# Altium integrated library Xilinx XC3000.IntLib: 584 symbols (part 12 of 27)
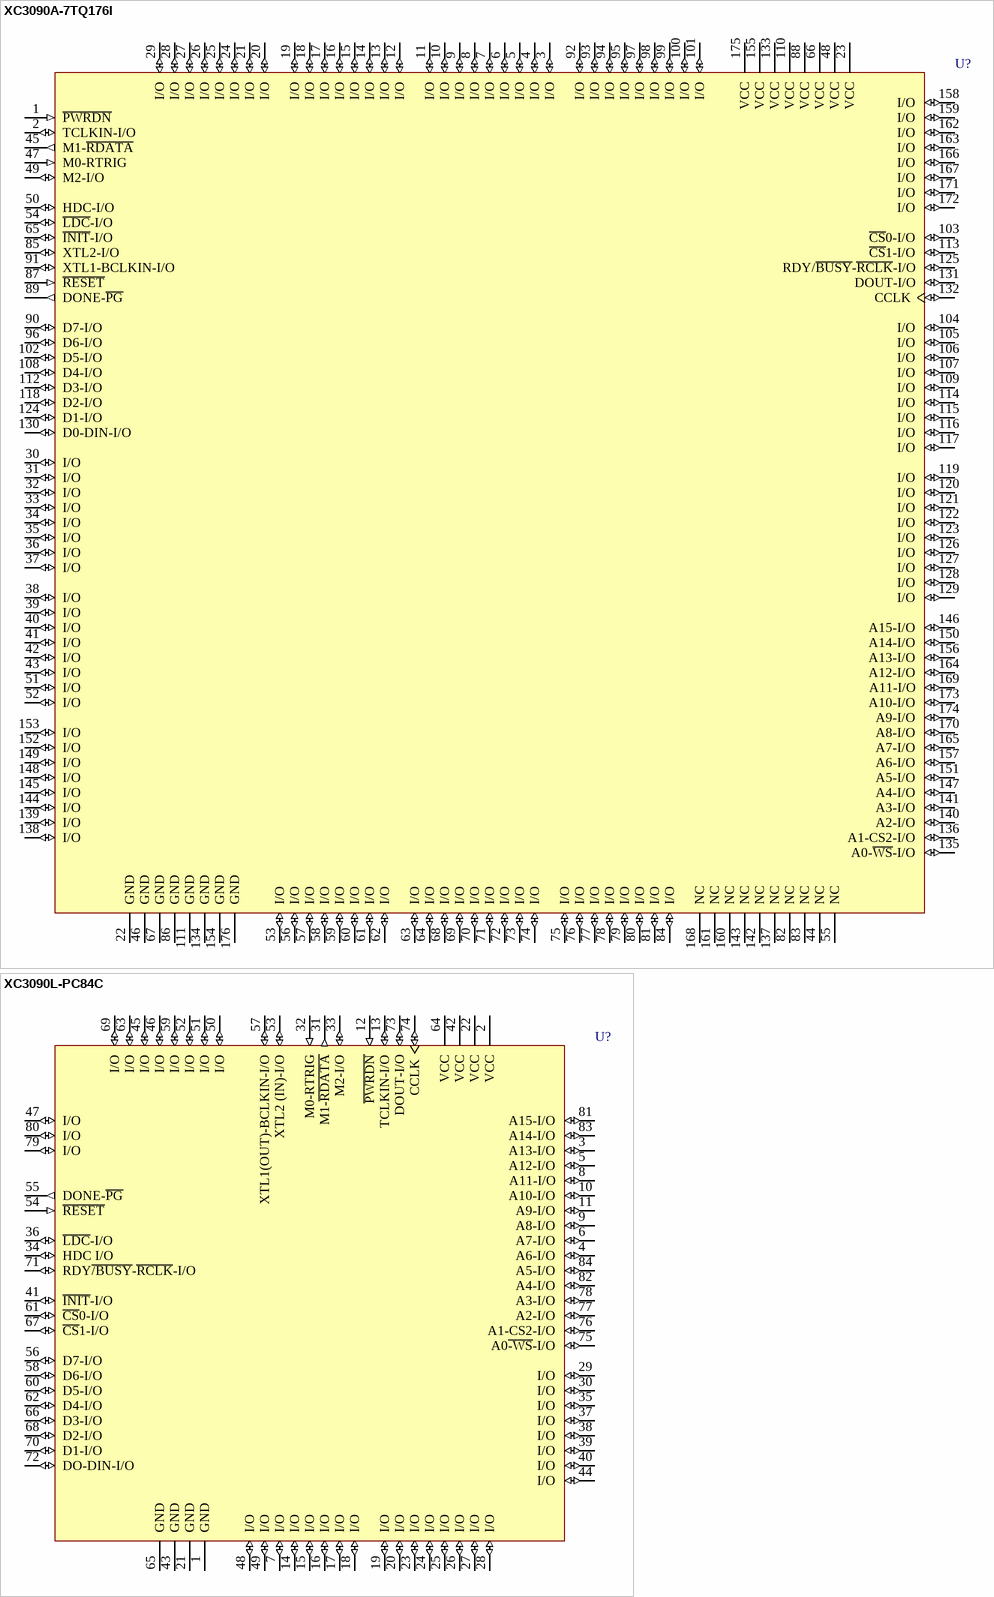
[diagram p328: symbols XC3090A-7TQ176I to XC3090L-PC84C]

## XC3090A-7TQ176I
designator U?
Logic Cell Array with 320 CLBs, with 144 I/O Pins, 176-Pin TQFP, Industrial Grade; ComponentAvailability: Not for New Design
footprint TQ176_N (Thin QFP, 176-Leads, Body 24x24mm, Pitch 0.5mm, IPC Medium Density)
footprint TQ176_L (Thin QFP, 176-Leads, Body 24x24mm, Pitch 0.5mm, IPC High Density)
footprint TQ176_M (Thin QFP, 176-Leads, Body 24x24mm, Pitch 0.5mm, IPC Low Density)
3D model XC3090A-TQ176 (176-Pin Thin Quad Flat Pack (TQ176))
pins: 1 ~{PWRDN} (in), 2 TCLKIN-I/O (io), 3 I/O (io), 4 I/O (io), 5 I/O (io), 6 I/O (io), 7 I/O (io), 8 I/O (io), 9 I/O (io), 10 I/O (io), 11 I/O (io), 12 I/O (io), 13 I/O (io), 14 I/O (io), 15 I/O (io), 16 I/O (io), 17 I/O (io), 18 I/O (io), 19 I/O (io), 20 I/O (io), 21 I/O (io), 22 GND (power), 23 VCC (power), 24 I/O (io), 25 I/O (io), 26 I/O (io), 27 I/O (io), 28 I/O (io), 29 I/O (io), 30 I/O (io), 31 I/O (io), 32 I/O (io), 33 I/O (io), 34 I/O (io), 35 I/O (io), 36 I/O (io), 37 I/O (io), 38 I/O (io), 39 I/O (io), 40 I/O (io), 41 I/O (io), 42 I/O (io), 43 I/O (io), 44 NC, 45 M1-~{RDATA} (out), 46 GND (power), 47 M0-RTRIG (in), 48 VCC (power), 49 M2-I/O (io), 50 HDC-I/O (io), 51 I/O (io), 52 I/O (io), 53 I/O (io), 54 ~{LDC}-I/O (io), 55 NC, 56 I/O (io), 57 I/O (io), 58 I/O (io), 59 I/O (io), 60 I/O (io), 61 I/O (io), 62 I/O (io), 63 I/O (io), 64 I/O (io), 65 ~{INIT}-I/O (io), 66 VCC (power), 67 GND (power), 68 I/O (io), 69 I/O (io), 70 I/O (io), 71 I/O (io), 72 I/O (io), 73 I/O (io), 74 I/O (io), 75 I/O (io), 76 I/O (io), 77 I/O (io), 78 I/O (io), 79 I/O (io), 80 I/O (io), 81 I/O (io), 82 NC, 83 NC, 84 I/O (io), 85 XTL2-I/O (io), 86 GND (power), 87 ~{RESET} (in), 88 VCC (power), 89 DONE-~{PG} (out), 90 D7-I/O (io), 91 XTL1-BCLKIN-I/O (io), 92 I/O (io), 93 I/O (io), 94 I/O (io), 95 I/O (io), 96 D6-I/O (io), 97 I/O (io), 98 I/O (io), 99 I/O (io), 100 I/O (io), 101 I/O (io), 102 D5-I/O (io), 103 ~{CS}0-I/O (io), 104 I/O (io), 105 I/O (io), 106 I/O (io), 107 I/O (io), 108 D4-I/O (io), 109 I/O (io), 110 VCC (power), 111 GND (power), 112 D3-I/O (io), 113 ~{CS}1-I/O (io), 114 I/O (io), 115 I/O (io), 116 I/O (io), 117 I/O (io), 118 D2-I/O (io), 119 I/O (io), 120 I/O (io), 121 I/O (io), 122 I/O (io), 123 I/O (io), 124 D1-I/O (io), 125 RDY/~{BUSY}-~{RCLK}-I/O (io), 126 I/O (io), 127 I/O (io), 128 I/O (io), 129 I/O (io), 130 D0-DIN-I/O (io), 131 DOUT-I/O (io), 132 CCLK (io), 133 VCC (power), 134 GND (power), 135 A0-~{WS}-I/O (io), 136 A1-CS2-I/O (io), 137 NC, 138 I/O (io), 139 I/O (io), 140 A2-I/O (io), 141 A3-I/O (io), 142 NC, 143 NC, 144 I/O (io), 145 I/O (io), 146 A15-I/O (io), 147 A4-I/O (io), 148 I/O (io), 149 I/O (io), 150 A14-I/O (io), 151 A5-I/O (io), 152 I/O (io), 153 I/O (io), 154 GND (power), 155 VCC (power), 156 A13-I/O (io), 157 A6-I/O (io), 158 I/O (io), 159 I/O (io), 160 NC, 161 NC, 162 I/O (io), 163 I/O (io), 164 A12-I/O (io), 165 A7-I/O (io), 166 I/O (io), 167 I/O (io), 168 NC, 169 A11-I/O (io), 170 A8-I/O (io), 171 I/O (io), 172 I/O (io), 173 A10-I/O (io), 174 A9-I/O (io), 175 VCC (power), 176 GND (power)

## XC3090L-PC84C
designator U?
Logic Cell Array with 320 CLBs, with 70 I/O Pins, 84-Pin PLCC, Commercial Grade; ComponentAvailability: Not for New Design
footprint PC84_N (Leaded Chip Carrier, 84-Leads, Body 29.3x29.3mm, Pitch 1.27mm, IPC Medium Density)
footprint PC84_L (Leaded Chip Carrier, 84-Leads, Body 29.3x29.3mm, Pitch 1.27mm, IPC High Density)
footprint PC84_M (Leaded Chip Carrier, 84-Leads, Body 29.3x29.3mm, Pitch 1.27mm, IPC Low Density)
3D model XC3090L-PC84 (84-Pin Plastic Leaded Chip Carrier (PC84))
pins: 1 GND (power), 2 VCC (power), 3 A13-I/O (io), 4 A6-I/O (io), 5 A12-I/O (io), 6 A7-I/O (io), 7 I/O (io), 8 A11-I/O (io), 9 A8-I/O (io), 10 A10-I/O (io), 11 A9-I/O (io), 12 ~{PWRDN} (in), 13 TCLKIN-I/O (io), 14 I/O (io), 15 I/O (io), 16 I/O (io), 17 I/O (io), 18 I/O (io), 19 I/O (io), 20 I/O (io), 21 GND (power), 22 VCC (power), 23 I/O (io), 24 I/O (io), 25 I/O (io), 26 I/O (io), 27 I/O (io), 28 I/O (io), 29 I/O (io), 30 I/O (io), 31 M1-~{RDATA} (out), 32 M0-RTRIG (in), 33 M2-I/O (io), 34 HDC I/O (io), 35 I/O (io), 36 ~{LDC}-I/O (io), 37 I/O (io), 38 I/O (io), 39 I/O (io), 40 I/O (io), 41 ~{INIT}-I/O (io), 42 VCC (power), 43 GND (power), 44 I/O (io), 45 I/O (io), 46 I/O (io), 47 I/O (io), 48 I/O (io), 49 I/O (io), 50 I/O (io), 51 I/O (io), 52 I/O (io), 53 XTL2 (IN)-I/O (io), 54 ~{RESET} (in), 55 DONE-~{PG} (out), 56 D7-I/O (io), 57 XTL1(OUT)-BCLKIN-I/O (io), 58 D6-I/O (io), 59 I/O (io), 60 D5-I/O (io), 61 ~{CS}0-I/O (io), 62 D4-I/O (io), 63 I/O (io), 64 VCC (power), 65 GND (power), 66 D3-I/O (io), 67 ~{CS}1-I/O (io), 68 D2-I/O (io), 69 I/O (io), 70 D1-I/O (io), 71 RDY~{/BUSY}-~{RCLK}-I/O (io), 72 DO-DIN-I/O (io), 73 DOUT-I/O (io), 74 CCLK (io), 75 A0~{-WS}-I/O (io), 76 A1-CS2-I/O (io), 77 A2-I/O (io), 78 A3-I/O (io), 79 I/O (io), 80 I/O (io), 81 A15-I/O (io), 82 A4-I/O (io), 83 A14-I/O (io), 84 A5-I/O (io)

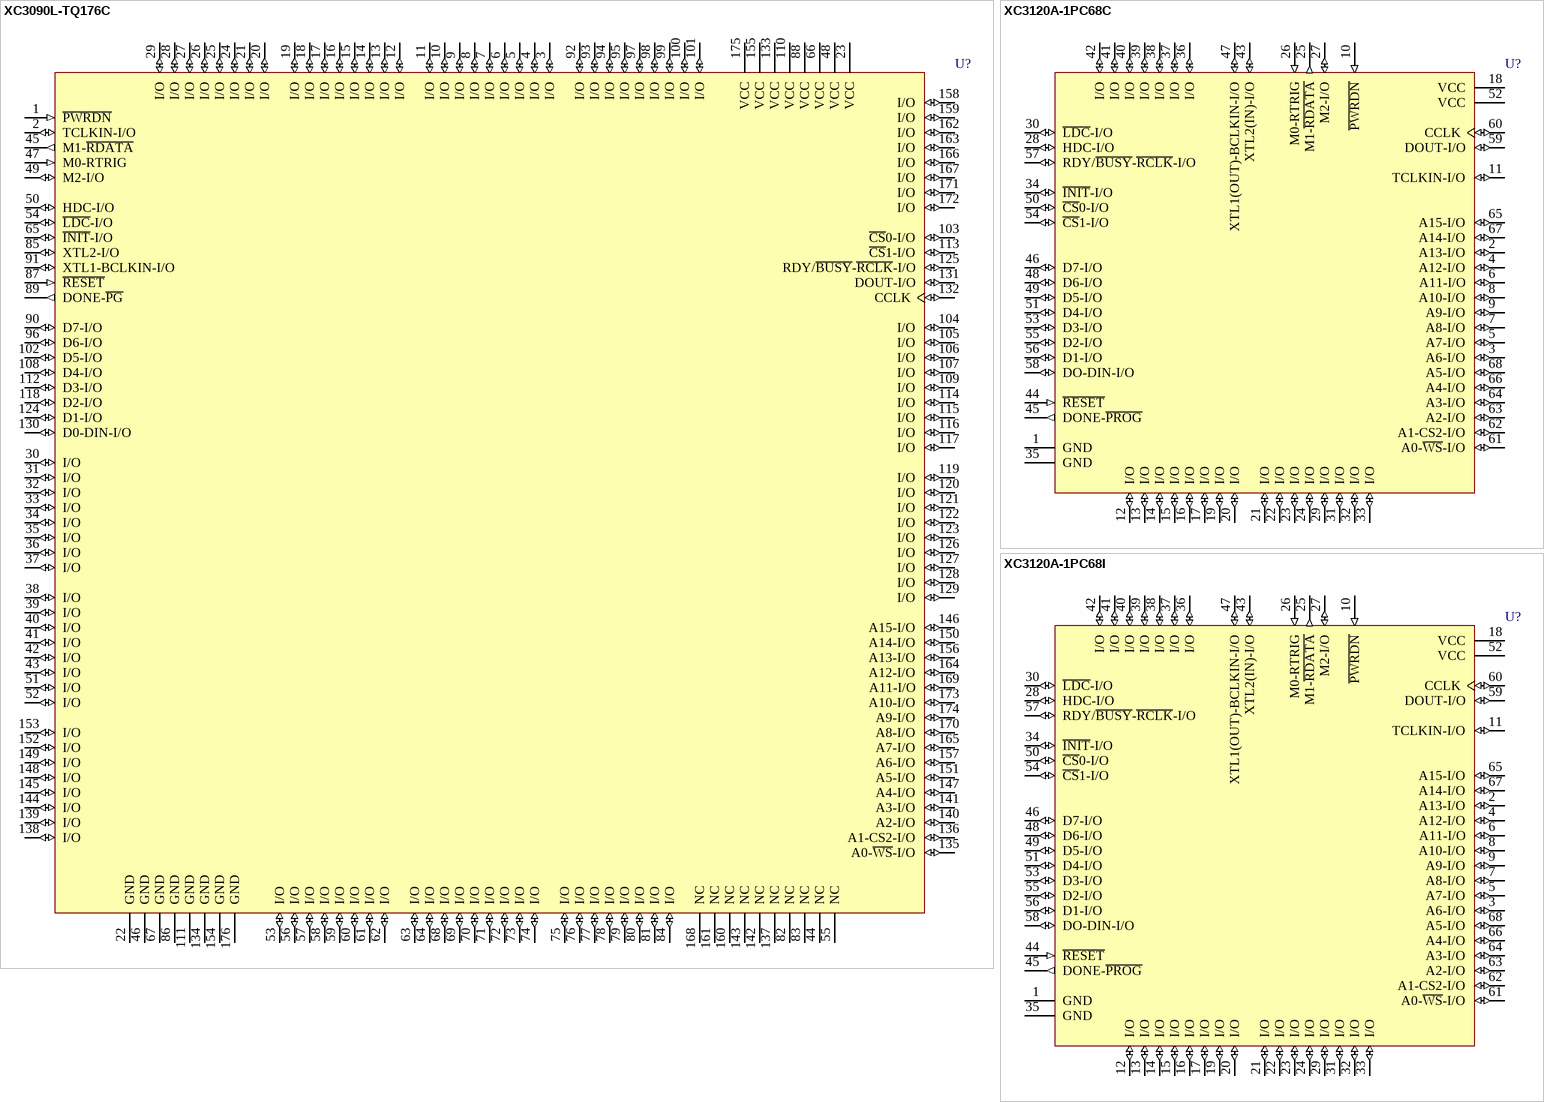
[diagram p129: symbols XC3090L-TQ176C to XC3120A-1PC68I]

## XC3090L-TQ176C
designator U?
Logic Cell Array with 320 CLBs, with 144 I/O Pins, 176-Pin TQFP, Commercial Grade; ComponentAvailability: Not for New Design
footprint TQ176_N (Thin QFP, 176-Leads, Body 24x24mm, Pitch 0.5mm, IPC Medium Density)
footprint TQ176_L (Thin QFP, 176-Leads, Body 24x24mm, Pitch 0.5mm, IPC High Density)
footprint TQ176_M (Thin QFP, 176-Leads, Body 24x24mm, Pitch 0.5mm, IPC Low Density)
3D model XC3090L-TQ176 (176-Pin Thin Quad Flat Pack (TQ176))
pins: 1 ~{PWRDN} (in), 2 TCLKIN-I/O (io), 3 I/O (io), 4 I/O (io), 5 I/O (io), 6 I/O (io), 7 I/O (io), 8 I/O (io), 9 I/O (io), 10 I/O (io), 11 I/O (io), 12 I/O (io), 13 I/O (io), 14 I/O (io), 15 I/O (io), 16 I/O (io), 17 I/O (io), 18 I/O (io), 19 I/O (io), 20 I/O (io), 21 I/O (io), 22 GND (power), 23 VCC (power), 24 I/O (io), 25 I/O (io), 26 I/O (io), 27 I/O (io), 28 I/O (io), 29 I/O (io), 30 I/O (io), 31 I/O (io), 32 I/O (io), 33 I/O (io), 34 I/O (io), 35 I/O (io), 36 I/O (io), 37 I/O (io), 38 I/O (io), 39 I/O (io), 40 I/O (io), 41 I/O (io), 42 I/O (io), 43 I/O (io), 44 NC, 45 M1-~{RDATA} (out), 46 GND (power), 47 M0-RTRIG (in), 48 VCC (power), 49 M2-I/O (io), 50 HDC-I/O (io), 51 I/O (io), 52 I/O (io), 53 I/O (io), 54 ~{LDC}-I/O (io), 55 NC, 56 I/O (io), 57 I/O (io), 58 I/O (io), 59 I/O (io), 60 I/O (io), 61 I/O (io), 62 I/O (io), 63 I/O (io), 64 I/O (io), 65 ~{INIT}-I/O (io), 66 VCC (power), 67 GND (power), 68 I/O (io), 69 I/O (io), 70 I/O (io), 71 I/O (io), 72 I/O (io), 73 I/O (io), 74 I/O (io), 75 I/O (io), 76 I/O (io), 77 I/O (io), 78 I/O (io), 79 I/O (io), 80 I/O (io), 81 I/O (io), 82 NC, 83 NC, 84 I/O (io), 85 XTL2-I/O (io), 86 GND (power), 87 ~{RESET} (in), 88 VCC (power), 89 DONE-~{PG} (out), 90 D7-I/O (io), 91 XTL1-BCLKIN-I/O (io), 92 I/O (io), 93 I/O (io), 94 I/O (io), 95 I/O (io), 96 D6-I/O (io), 97 I/O (io), 98 I/O (io), 99 I/O (io), 100 I/O (io), 101 I/O (io), 102 D5-I/O (io), 103 ~{CS}0-I/O (io), 104 I/O (io), 105 I/O (io), 106 I/O (io), 107 I/O (io), 108 D4-I/O (io), 109 I/O (io), 110 VCC (power), 111 GND (power), 112 D3-I/O (io), 113 ~{CS}1-I/O (io), 114 I/O (io), 115 I/O (io), 116 I/O (io), 117 I/O (io), 118 D2-I/O (io), 119 I/O (io), 120 I/O (io), 121 I/O (io), 122 I/O (io), 123 I/O (io), 124 D1-I/O (io), 125 RDY/~{BUSY}-~{RCLK}-I/O (io), 126 I/O (io), 127 I/O (io), 128 I/O (io), 129 I/O (io), 130 D0-DIN-I/O (io), 131 DOUT-I/O (io), 132 CCLK (io), 133 VCC (power), 134 GND (power), 135 A0-~{WS}-I/O (io), 136 A1-CS2-I/O (io), 137 NC, 138 I/O (io), 139 I/O (io), 140 A2-I/O (io), 141 A3-I/O (io), 142 NC, 143 NC, 144 I/O (io), 145 I/O (io), 146 A15-I/O (io), 147 A4-I/O (io), 148 I/O (io), 149 I/O (io), 150 A14-I/O (io), 151 A5-I/O (io), 152 I/O (io), 153 I/O (io), 154 GND (power), 155 VCC (power), 156 A13-I/O (io), 157 A6-I/O (io), 158 I/O (io), 159 I/O (io), 160 NC, 161 NC, 162 I/O (io), 163 I/O (io), 164 A12-I/O (io), 165 A7-I/O (io), 166 I/O (io), 167 I/O (io), 168 NC, 169 A11-I/O (io), 170 A8-I/O (io), 171 I/O (io), 172 I/O (io), 173 A10-I/O (io), 174 A9-I/O (io), 175 VCC (power), 176 GND (power)

## XC3120A-1PC68C
designator U?
Logic Cell Array with 64 CLBs, with 58 I/O Pins, 68-Pin PLCC, Commercial Grade; ComponentAvailability: Not for New Design
footprint PC68_N (Leaded Chip Carrier, 68-Leads, Body 24x24mm, Pitch 1.27mm, IPC Medium Density)
footprint PC68_L (Leaded Chip Carrier, 68-Leads, Body 24x24mm, Pitch 1.27mm, IPC High Density)
footprint PC68_M (Leaded Chip Carrier, 68-Leads, Body 24x24mm, Pitch 1.27mm, IPC Low Density)
3D model XC3120A-PC68 (68-Pin Plastic Leaded Chip Carrier (PC68))
pins: 1 GND (power), 2 A13-I/O (io), 3 A6-I/O (io), 4 A12-I/O (io), 5 A7-I/O (io), 6 A11-I/O (io), 7 A8-I/O (io), 8 A10-I/O (io), 9 A9-I/O (io), 10 ~{PWRDN} (in), 11 TCLKIN-I/O (io), 12 I/O (io), 13 I/O (io), 14 I/O (io), 15 I/O (io), 16 I/O (io), 17 I/O (io), 18 VCC (power), 19 I/O (io), 20 I/O (io), 21 I/O (io), 22 I/O (io), 23 I/O (io), 24 I/O (io), 25 M1-~{RDATA} (out), 26 M0-RTRIG (in), 27 M2-I/O (io), 28 HDC-I/O (io), 29 I/O (io), 30 ~{LDC}-I/O (io), 31 I/O (io), 32 I/O (io), 33 I/O (io), 34 ~{INIT}-I/O (io), 35 GND (power), 36 I/O (io), 37 I/O (io), 38 I/O (io), 39 I/O (io), 40 I/O (io), 41 I/O (io), 42 I/O (io), 43 XTL2(IN)-I/O (io), 44 ~{RESET} (in), 45 DONE-~{PROG} (out), 46 D7-I/O (io), 47 XTL1(OUT)-BCLKIN-I/O (io), 48 D6-I/O (io), 49 D5-I/O (io), 50 ~{CS}0-I/O (io), 51 D4-I/O (io), 52 VCC (power), 53 D3-I/O (io), 54 ~{CS}1-I/O (io), 55 D2-I/O (io), 56 D1-I/O (io), 57 RDY/~{BUSY}-~{RCLK}-I/O (io), 58 DO-DIN-I/O (io), 59 DOUT-I/O (io), 60 CCLK (io), 61 A0-~{WS}-I/O (io), 62 A1-CS2-I/O (io), 63 A2-I/O (io), 64 A3-I/O (io), 65 A15-I/O (io), 66 A4-I/O (io), 67 A14-I/O (io), 68 A5-I/O (io)

## XC3120A-1PC68I
designator U?
Logic Cell Array with 64 CLBs, with 58 I/O Pins, 68-Pin PLCC, Industrial Grade; ComponentAvailability: Not for New Design
footprint PC68_N (Leaded Chip Carrier, 68-Leads, Body 24x24mm, Pitch 1.27mm, IPC Medium Density)
footprint PC68_L (Leaded Chip Carrier, 68-Leads, Body 24x24mm, Pitch 1.27mm, IPC High Density)
footprint PC68_M (Leaded Chip Carrier, 68-Leads, Body 24x24mm, Pitch 1.27mm, IPC Low Density)
3D model XC3120A-PC68 (68-Pin Plastic Leaded Chip Carrier (PC68))
pins: 1 GND (power), 2 A13-I/O (io), 3 A6-I/O (io), 4 A12-I/O (io), 5 A7-I/O (io), 6 A11-I/O (io), 7 A8-I/O (io), 8 A10-I/O (io), 9 A9-I/O (io), 10 ~{PWRDN} (in), 11 TCLKIN-I/O (io), 12 I/O (io), 13 I/O (io), 14 I/O (io), 15 I/O (io), 16 I/O (io), 17 I/O (io), 18 VCC (power), 19 I/O (io), 20 I/O (io), 21 I/O (io), 22 I/O (io), 23 I/O (io), 24 I/O (io), 25 M1-~{RDATA} (out), 26 M0-RTRIG (in), 27 M2-I/O (io), 28 HDC-I/O (io), 29 I/O (io), 30 ~{LDC}-I/O (io), 31 I/O (io), 32 I/O (io), 33 I/O (io), 34 ~{INIT}-I/O (io), 35 GND (power), 36 I/O (io), 37 I/O (io), 38 I/O (io), 39 I/O (io), 40 I/O (io), 41 I/O (io), 42 I/O (io), 43 XTL2(IN)-I/O (io), 44 ~{RESET} (in), 45 DONE-~{PROG} (out), 46 D7-I/O (io), 47 XTL1(OUT)-BCLKIN-I/O (io), 48 D6-I/O (io), 49 D5-I/O (io), 50 ~{CS}0-I/O (io), 51 D4-I/O (io), 52 VCC (power), 53 D3-I/O (io), 54 ~{CS}1-I/O (io), 55 D2-I/O (io), 56 D1-I/O (io), 57 RDY/~{BUSY}-~{RCLK}-I/O (io), 58 DO-DIN-I/O (io), 59 DOUT-I/O (io), 60 CCLK (io), 61 A0-~{WS}-I/O (io), 62 A1-CS2-I/O (io), 63 A2-I/O (io), 64 A3-I/O (io), 65 A15-I/O (io), 66 A4-I/O (io), 67 A14-I/O (io), 68 A5-I/O (io)

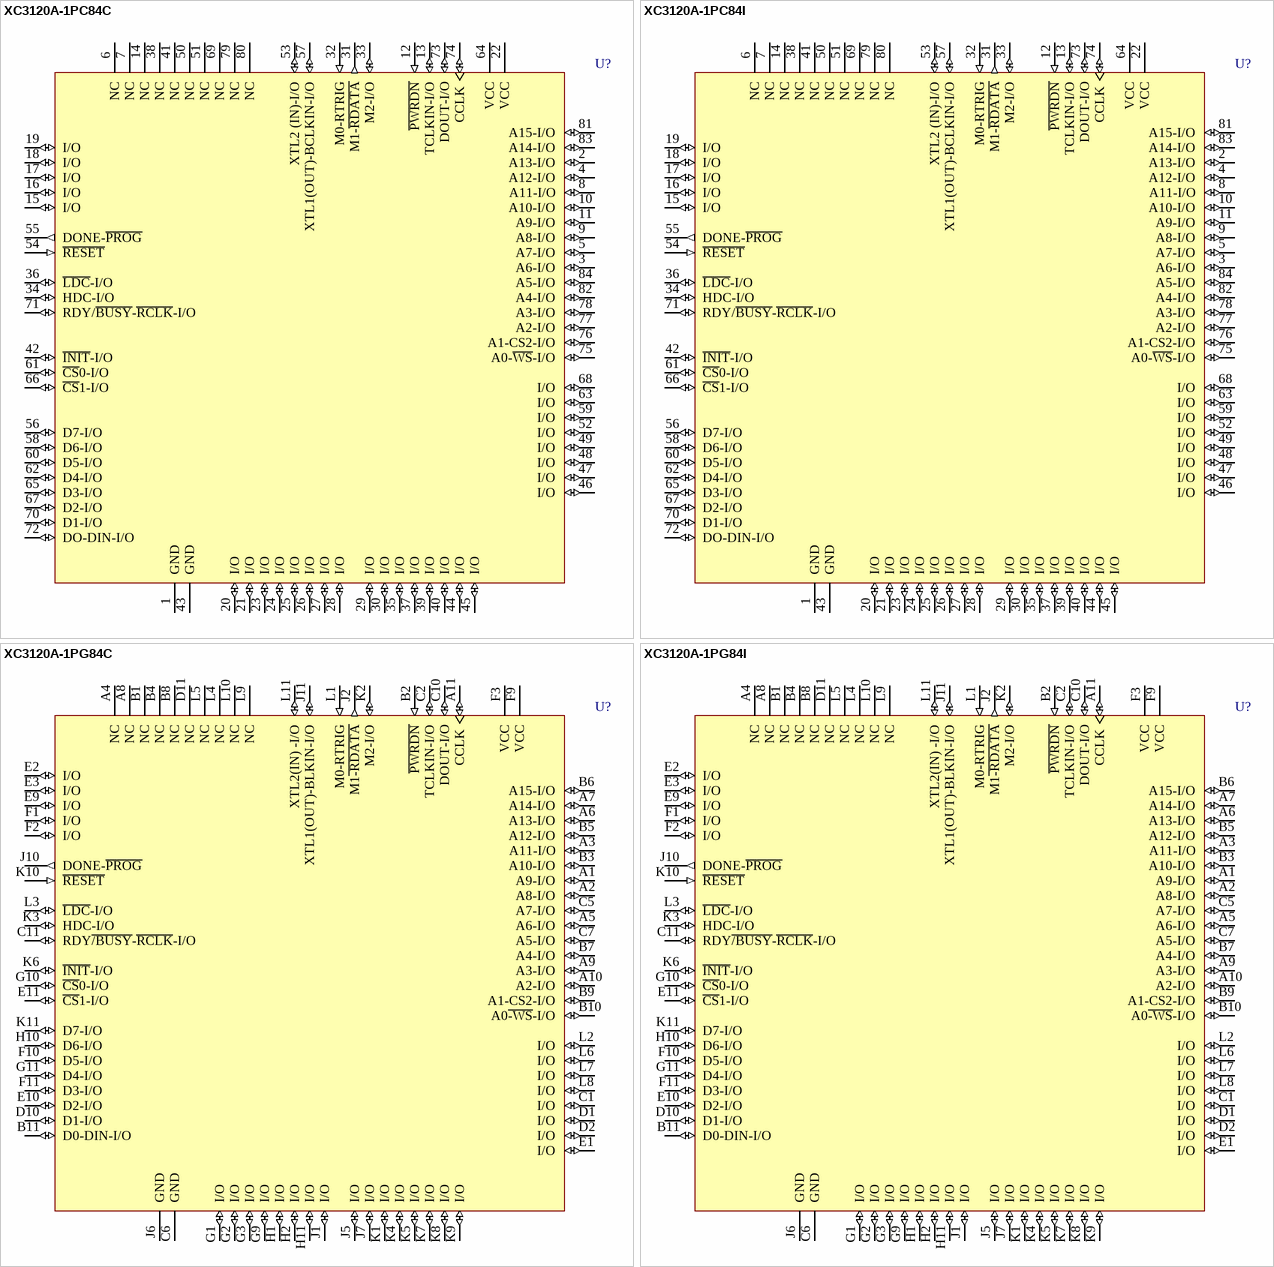
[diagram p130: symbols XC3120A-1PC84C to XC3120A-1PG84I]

## XC3120A-1PC84C
designator U?
Logic Cell Array with 64 CLBs, with 64 I/O Pins, 84-Pin PLCC, Commercial Grade; ComponentAvailability: Not for New Design
footprint PC84_N (Leaded Chip Carrier, 84-Leads, Body 29.3x29.3mm, Pitch 1.27mm, IPC Medium Density)
footprint PC84_L (Leaded Chip Carrier, 84-Leads, Body 29.3x29.3mm, Pitch 1.27mm, IPC High Density)
footprint PC84_M (Leaded Chip Carrier, 84-Leads, Body 29.3x29.3mm, Pitch 1.27mm, IPC Low Density)
3D model XC3120A-PC84 (84-Pin Plastic Leaded Chip Carrier (PC84))
pins: 1 GND (power), 2 A13-I/O (io), 3 A6-I/O (io), 4 A12-I/O (io), 5 A7-I/O (io), 6 NC, 7 NC, 8 A11-I/O (io), 9 A8-I/O (io), 10 A10-I/O (io), 11 A9-I/O (io), 12 ~{PWRDN} (in), 13 TCLKIN-I/O (io), 14 NC, 15 I/O (io), 16 I/O (io), 17 I/O (io), 18 I/O (io), 19 I/O (io), 20 I/O (io), 21 I/O (io), 22 VCC (power), 23 I/O (io), 24 I/O (io), 25 I/O (io), 26 I/O (io), 27 I/O (io), 28 I/O (io), 29 I/O (io), 30 I/O (io), 31 M1-~{RDATA} (out), 32 M0-RTRIG (in), 33 M2-I/O (io), 34 HDC-I/O (io), 35 I/O (io), 36 ~{LDC}-I/O (io), 37 I/O (io), 38 NC, 39 I/O (io), 40 I/O (io), 41 NC, 42 ~{INIT}-I/O (io), 43 GND (power), 44 I/O (io), 45 I/O (io), 46 I/O (io), 47 I/O (io), 48 I/O (io), 49 I/O (io), 50 NC, 51 NC, 52 I/O (io), 53 XTL2 (IN)-I/O (io), 54 ~{RESET} (in), 55 DONE-~{PROG} (out), 56 D7-I/O (io), 57 XTL1(OUT)-BCLKIN-I/O (io), 58 D6-I/O (io), 59 I/O (io), 60 D5-I/O (io), 61 ~{CS}0-I/O (io), 62 D4-I/O (io), 63 I/O (io), 64 VCC (power), 65 D3-I/O (io), 66 ~{CS}1-I/O (io), 67 D2-I/O (io), 68 I/O (io), 69 NC, 70 D1-I/O (io), 71 RDY/~{BUSY}-~{RCLK}-I/O (io), 72 DO-DIN-I/O (io), 73 DOUT-I/O (io), 74 CCLK (io), 75 A0-~{WS}-I/O (io), 76 A1-CS2-I/O (io), 77 A2-I/O (io), 78 A3-I/O (io), 79 NC, 80 NC, 81 A15-I/O (io), 82 A4-I/O (io), 83 A14-I/O (io), 84 A5-I/O (io)

## XC3120A-1PC84I
designator U?
Logic Cell Array with 64 CLBs, with 64 I/O Pins, 84-Pin PLCC, Industrial Grade; ComponentAvailability: Not for New Design
footprint PC84_N (Leaded Chip Carrier, 84-Leads, Body 29.3x29.3mm, Pitch 1.27mm, IPC Medium Density)
footprint PC84_L (Leaded Chip Carrier, 84-Leads, Body 29.3x29.3mm, Pitch 1.27mm, IPC High Density)
footprint PC84_M (Leaded Chip Carrier, 84-Leads, Body 29.3x29.3mm, Pitch 1.27mm, IPC Low Density)
3D model XC3120A-PC84 (84-Pin Plastic Leaded Chip Carrier (PC84))
pins: 1 GND (power), 2 A13-I/O (io), 3 A6-I/O (io), 4 A12-I/O (io), 5 A7-I/O (io), 6 NC, 7 NC, 8 A11-I/O (io), 9 A8-I/O (io), 10 A10-I/O (io), 11 A9-I/O (io), 12 ~{PWRDN} (in), 13 TCLKIN-I/O (io), 14 NC, 15 I/O (io), 16 I/O (io), 17 I/O (io), 18 I/O (io), 19 I/O (io), 20 I/O (io), 21 I/O (io), 22 VCC (power), 23 I/O (io), 24 I/O (io), 25 I/O (io), 26 I/O (io), 27 I/O (io), 28 I/O (io), 29 I/O (io), 30 I/O (io), 31 M1-~{RDATA} (out), 32 M0-RTRIG (in), 33 M2-I/O (io), 34 HDC-I/O (io), 35 I/O (io), 36 ~{LDC}-I/O (io), 37 I/O (io), 38 NC, 39 I/O (io), 40 I/O (io), 41 NC, 42 ~{INIT}-I/O (io), 43 GND (power), 44 I/O (io), 45 I/O (io), 46 I/O (io), 47 I/O (io), 48 I/O (io), 49 I/O (io), 50 NC, 51 NC, 52 I/O (io), 53 XTL2 (IN)-I/O (io), 54 ~{RESET} (in), 55 DONE-~{PROG} (out), 56 D7-I/O (io), 57 XTL1(OUT)-BCLKIN-I/O (io), 58 D6-I/O (io), 59 I/O (io), 60 D5-I/O (io), 61 ~{CS}0-I/O (io), 62 D4-I/O (io), 63 I/O (io), 64 VCC (power), 65 D3-I/O (io), 66 ~{CS}1-I/O (io), 67 D2-I/O (io), 68 I/O (io), 69 NC, 70 D1-I/O (io), 71 RDY/~{BUSY}-~{RCLK}-I/O (io), 72 DO-DIN-I/O (io), 73 DOUT-I/O (io), 74 CCLK (io), 75 A0-~{WS}-I/O (io), 76 A1-CS2-I/O (io), 77 A2-I/O (io), 78 A3-I/O (io), 79 NC, 80 NC, 81 A15-I/O (io), 82 A4-I/O (io), 83 A14-I/O (io), 84 A5-I/O (io)

## XC3120A-1PG84C
designator U?
Logic Cell Array with 64 CLBs, with 64 I/O Pins, 84-Pin PGA, Commercial Grade; ComponentAvailability: Not for New Design
footprint PG84 (PGA, 85-Leads, Body 28x28mm, Pitch 2.54mm)
3D model XC3120A-PG84 (84-Pin Ceramic Pin Grid Array (PG84))
pins: A1 A9-I/O (io), A2 A8-I/O (io), A3 A11-I/O (io), A4 NC, A5 A6-I/O (io), A6 A13-I/O (io), A7 A14-I/O (io), A8 NC, A9 A3-I/O (io), A10 A2-I/O (io), A11 CCLK (io), B1 NC, B2 ~{PWRDN} (in), B3 A10-I/O (io), B4 NC, B5 A12-I/O (io), B6 A15-I/O (io), B7 A4-I/O (io), B8 NC, B9 A1-CS2-I/O (io), B10 A0~{-WS}-I/O (io), B11 D0-DIN-I/O (io), C1 I/O (io), C2 TCLKIN-I/O (io), C5 A7-I/O (io), C6 GND (power), C7 A5-I/O (io), C10 DOUT-I/O (io), C11 RDY~{/BUSY}-~{RCLK}-I/O (io), D1 I/O (io), D2 I/O (io), D10 D1-I/O (io), D11 NC, E1 I/O (io), E2 I/O (io), E3 I/O (io), E9 I/O (io), E10 D2-I/O (io), E11 ~{CS}1-I/O (io), F1 I/O (io), F2 I/O (io), F3 VCC (power), F9 VCC (power), F10 D5-I/O (io), F11 D3-I/O (io), G1 I/O (io), G2 I/O (io), G3 I/O (io), G9 I/O (io), G10 ~{CS}0-I/O (io), G11 D4-I/O (io), H1 I/O (io), H2 I/O (io), H10 D6-I/O (io), H11 I/O (io), J1 I/O (io), J2 M1~{-RDATA} (out), J5 I/O (io), J6 GND (power), J7 I/O (io), J10 DONE-~{PROG} (out), J11 XTL1(OUT)-BLKIN-I/O (io), K1 I/O (io), K2 M2-I/O (io), K3 HDC-I/O (io), K4 I/O (io), K5 I/O (io), K6 ~{INIT}-I/O (io), K7 I/O (io), K8 I/O (io), K9 I/O (io), K10 ~{RESET} (in), K11 D7-I/O (io), L1 M0-RTRIG (in), L2 I/O (io), L3 ~{LDC}-I/O (io), L4 NC, L5 NC, L6 I/O (io), L7 I/O (io), L8 I/O (io), L9 NC, L10 NC, L11 XTL2(IN) -I/O (io)

## XC3120A-1PG84I
designator U?
Logic Cell Array with 64 CLBs, with 64 I/O Pins, 84-Pin PGA, Industrial Grade; ComponentAvailability: Not for New Design
footprint PG84 (PGA, 85-Leads, Body 28x28mm, Pitch 2.54mm)
3D model XC3120A-PG84 (84-Pin Ceramic Pin Grid Array (PG84))
pins: A1 A9-I/O (io), A2 A8-I/O (io), A3 A11-I/O (io), A4 NC, A5 A6-I/O (io), A6 A13-I/O (io), A7 A14-I/O (io), A8 NC, A9 A3-I/O (io), A10 A2-I/O (io), A11 CCLK (io), B1 NC, B2 ~{PWRDN} (in), B3 A10-I/O (io), B4 NC, B5 A12-I/O (io), B6 A15-I/O (io), B7 A4-I/O (io), B8 NC, B9 A1-CS2-I/O (io), B10 A0~{-WS}-I/O (io), B11 D0-DIN-I/O (io), C1 I/O (io), C2 TCLKIN-I/O (io), C5 A7-I/O (io), C6 GND (power), C7 A5-I/O (io), C10 DOUT-I/O (io), C11 RDY~{/BUSY}-~{RCLK}-I/O (io), D1 I/O (io), D2 I/O (io), D10 D1-I/O (io), D11 NC, E1 I/O (io), E2 I/O (io), E3 I/O (io), E9 I/O (io), E10 D2-I/O (io), E11 ~{CS}1-I/O (io), F1 I/O (io), F2 I/O (io), F3 VCC (power), F9 VCC (power), F10 D5-I/O (io), F11 D3-I/O (io), G1 I/O (io), G2 I/O (io), G3 I/O (io), G9 I/O (io), G10 ~{CS}0-I/O (io), G11 D4-I/O (io), H1 I/O (io), H2 I/O (io), H10 D6-I/O (io), H11 I/O (io), J1 I/O (io), J2 M1~{-RDATA} (out), J5 I/O (io), J6 GND (power), J7 I/O (io), J10 DONE-~{PROG} (out), J11 XTL1(OUT)-BLKIN-I/O (io), K1 I/O (io), K2 M2-I/O (io), K3 HDC-I/O (io), K4 I/O (io), K5 I/O (io), K6 ~{INIT}-I/O (io), K7 I/O (io), K8 I/O (io), K9 I/O (io), K10 ~{RESET} (in), K11 D7-I/O (io), L1 M0-RTRIG (in), L2 I/O (io), L3 ~{LDC}-I/O (io), L4 NC, L5 NC, L6 I/O (io), L7 I/O (io), L8 I/O (io), L9 NC, L10 NC, L11 XTL2(IN) -I/O (io)

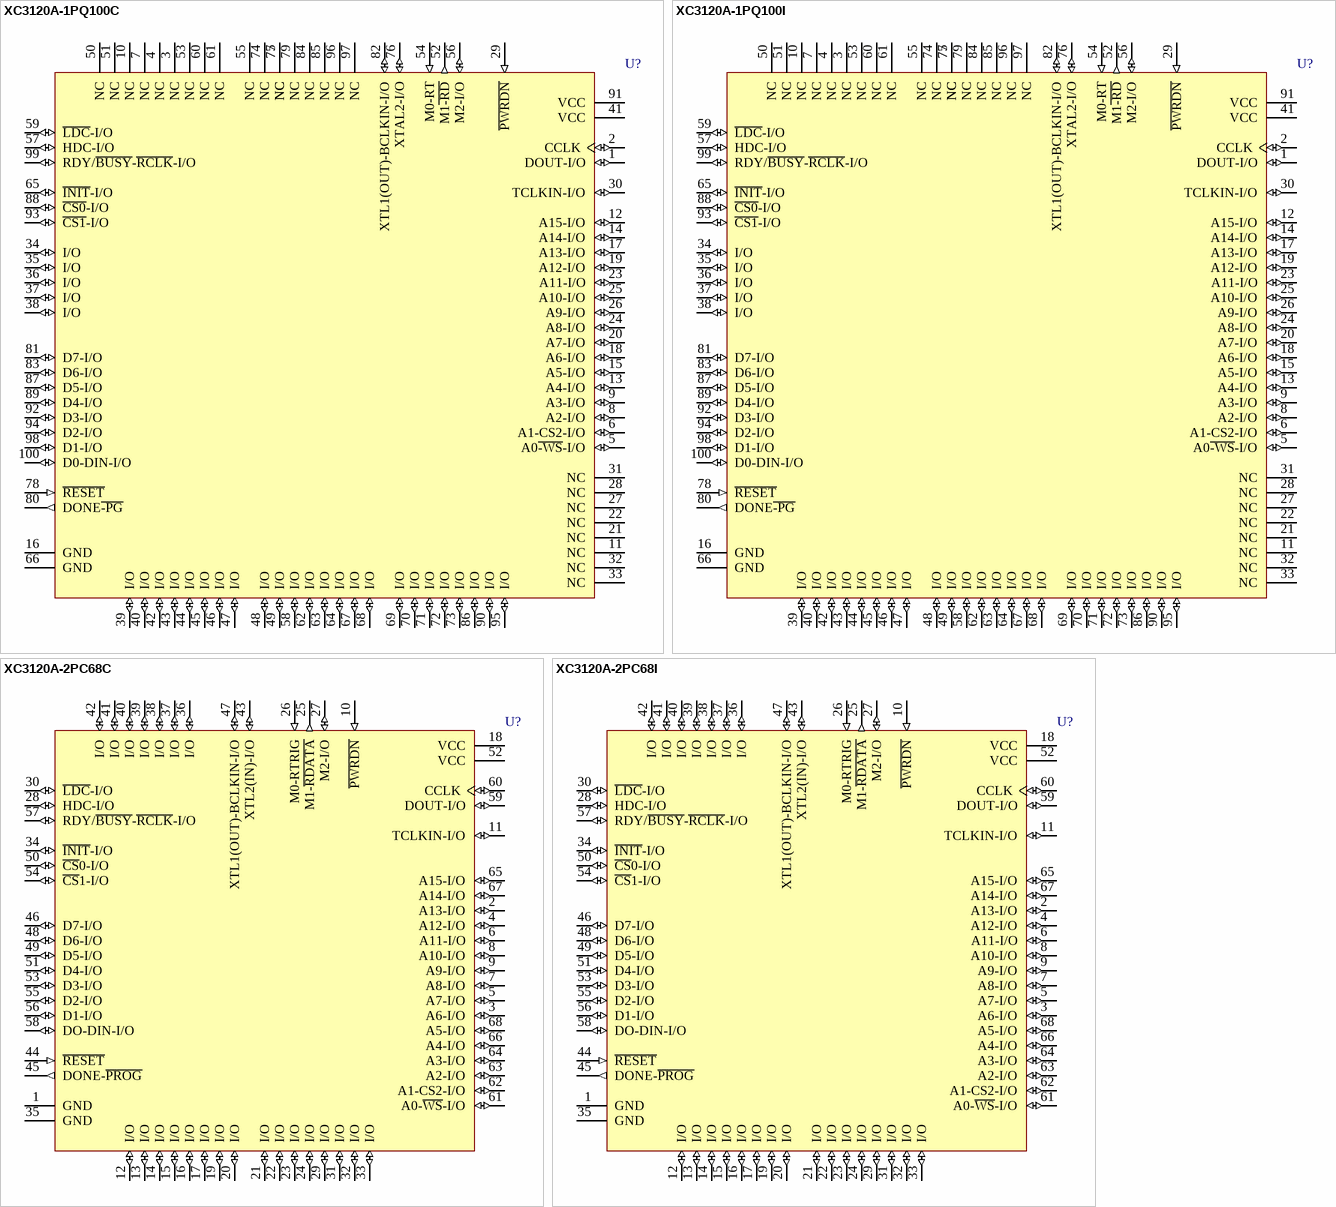
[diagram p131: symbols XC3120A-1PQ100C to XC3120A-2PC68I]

## XC3120A-1PQ100C
designator U?
Logic Cell Array with 64 CLBs, with 64 I/O Pins, 100-Pin PQFP, Commercial Grade; ComponentAvailability: Not for New Design
footprint PQ100_N (QFP, 100-Leads, Body 20x14mm, Pitch 0.65mm, IPC Medium Density)
footprint PQ100_L (QFP, 100-Leads, Body 20x14mm, Pitch 0.65mm, IPC High Density)
footprint PQ100_M (QFP, 100-Leads, Body 20x14mm, Pitch 0.65mm, IPC Low Density)
3D model XC3120A-PQ100 (100-Pin Plastic Quad Flat Pack (PQ100))
pins: 1 DOUT-I/O (io), 2 CCLK (io), 3 NC, 4 NC, 5 A0~{-WS}-I/O (io), 6 A1-CS2-I/O (io), 7 NC, 8 A2-I/O (io), 9 A3-I/O (io), 10 NC, 11 NC, 12 A15-I/O (io), 13 A4-I/O (io), 14 A14-I/O (io), 15 A5-I/O (io), 16 GND (power), 17 A13-I/O (io), 18 A6-I/O (io), 19 A12-I/O (io), 20 A7-I/O (io), 21 NC, 22 NC, 23 A11-I/O (io), 24 A8-I/O (io), 25 A10-I/O (io), 26 A9-I/O (io), 27 NC, 28 NC, 29 ~{PWRDN} (in), 30 TCLKIN-I/O (io), 31 NC, 32 NC, 33 NC, 34 I/O (io), 35 I/O (io), 36 I/O (io), 37 I/O (io), 38 I/O (io), 39 I/O (io), 40 I/O (io), 41 VCC (power), 42 I/O (io), 43 I/O (io), 44 I/O (io), 45 I/O (io), 46 I/O (io), 47 I/O (io), 48 I/O (io), 49 I/O (io), 50 NC, 51 NC, 52 M1~{-RD} (out), 53 NC, 54 M0-RT (in), 55 NC, 56 M2-I/O (io), 57 HDC-I/O (io), 58 I/O (io), 59 ~{LDC}-I/O (io), 60 NC, 61 NC, 62 I/O (io), 63 I/O (io), 64 I/O (io), 65 ~{INIT}-I/O (io), 66 GND (power), 67 I/O (io), 68 I/O (io), 69 I/O (io), 70 I/O (io), 71 I/O (io), 72 I/O (io), 73 I/O (io), 74 NC, 75 NC, 76 XTAL2-I/O (io), 77 NC, 78 ~{RESET} (in), 79 NC, 80 DONE~{-PG} (out), 81 D7-I/O (io), 82 XTL1(OUT)-BCLKIN-I/O (io), 83 D6-I/O (io), 84 NC, 85 NC, 86 I/O (io), 87 D5-I/O (io), 88 ~{CS0}-I/O (io), 89 D4-I/O (io), 90 I/O (io), 91 VCC (power), 92 D3-I/O (io), 93 ~{CS1}-I/O (io), 94 D2-I/O (io), 95 I/O (io), 96 NC, 97 NC, 98 D1-I/O (io), 99 RDY/~{BUSY}-~{RCLK}-I/O (io), 100 D0-DIN-I/O (io)

## XC3120A-1PQ100I
designator U?
Logic Cell Array with 64 CLBs, with 64 I/O Pins, 100-Pin PQFP, Industrial Grade; ComponentAvailability: Not for New Design
footprint PQ100_N (QFP, 100-Leads, Body 20x14mm, Pitch 0.65mm, IPC Medium Density)
footprint PQ100_L (QFP, 100-Leads, Body 20x14mm, Pitch 0.65mm, IPC High Density)
footprint PQ100_M (QFP, 100-Leads, Body 20x14mm, Pitch 0.65mm, IPC Low Density)
3D model XC3120A-PQ100 (100-Pin Plastic Quad Flat Pack (PQ100))
pins: 1 DOUT-I/O (io), 2 CCLK (io), 3 NC, 4 NC, 5 A0~{-WS}-I/O (io), 6 A1-CS2-I/O (io), 7 NC, 8 A2-I/O (io), 9 A3-I/O (io), 10 NC, 11 NC, 12 A15-I/O (io), 13 A4-I/O (io), 14 A14-I/O (io), 15 A5-I/O (io), 16 GND (power), 17 A13-I/O (io), 18 A6-I/O (io), 19 A12-I/O (io), 20 A7-I/O (io), 21 NC, 22 NC, 23 A11-I/O (io), 24 A8-I/O (io), 25 A10-I/O (io), 26 A9-I/O (io), 27 NC, 28 NC, 29 ~{PWRDN} (in), 30 TCLKIN-I/O (io), 31 NC, 32 NC, 33 NC, 34 I/O (io), 35 I/O (io), 36 I/O (io), 37 I/O (io), 38 I/O (io), 39 I/O (io), 40 I/O (io), 41 VCC (power), 42 I/O (io), 43 I/O (io), 44 I/O (io), 45 I/O (io), 46 I/O (io), 47 I/O (io), 48 I/O (io), 49 I/O (io), 50 NC, 51 NC, 52 M1~{-RD} (out), 53 NC, 54 M0-RT (in), 55 NC, 56 M2-I/O (io), 57 HDC-I/O (io), 58 I/O (io), 59 ~{LDC}-I/O (io), 60 NC, 61 NC, 62 I/O (io), 63 I/O (io), 64 I/O (io), 65 ~{INIT}-I/O (io), 66 GND (power), 67 I/O (io), 68 I/O (io), 69 I/O (io), 70 I/O (io), 71 I/O (io), 72 I/O (io), 73 I/O (io), 74 NC, 75 NC, 76 XTAL2-I/O (io), 77 NC, 78 ~{RESET} (in), 79 NC, 80 DONE~{-PG} (out), 81 D7-I/O (io), 82 XTL1(OUT)-BCLKIN-I/O (io), 83 D6-I/O (io), 84 NC, 85 NC, 86 I/O (io), 87 D5-I/O (io), 88 ~{CS0}-I/O (io), 89 D4-I/O (io), 90 I/O (io), 91 VCC (power), 92 D3-I/O (io), 93 ~{CS1}-I/O (io), 94 D2-I/O (io), 95 I/O (io), 96 NC, 97 NC, 98 D1-I/O (io), 99 RDY/~{BUSY}-~{RCLK}-I/O (io), 100 D0-DIN-I/O (io)

## XC3120A-2PC68C
designator U?
Logic Cell Array with 64 CLBs, with 58 I/O Pins, 68-Pin PLCC, Commercial Grade; ComponentAvailability: Not for New Design
footprint PC68_N (Leaded Chip Carrier, 68-Leads, Body 24x24mm, Pitch 1.27mm, IPC Medium Density)
footprint PC68_L (Leaded Chip Carrier, 68-Leads, Body 24x24mm, Pitch 1.27mm, IPC High Density)
footprint PC68_M (Leaded Chip Carrier, 68-Leads, Body 24x24mm, Pitch 1.27mm, IPC Low Density)
3D model XC3120A-PC68 (68-Pin Plastic Leaded Chip Carrier (PC68))
pins: 1 GND (power), 2 A13-I/O (io), 3 A6-I/O (io), 4 A12-I/O (io), 5 A7-I/O (io), 6 A11-I/O (io), 7 A8-I/O (io), 8 A10-I/O (io), 9 A9-I/O (io), 10 ~{PWRDN} (in), 11 TCLKIN-I/O (io), 12 I/O (io), 13 I/O (io), 14 I/O (io), 15 I/O (io), 16 I/O (io), 17 I/O (io), 18 VCC (power), 19 I/O (io), 20 I/O (io), 21 I/O (io), 22 I/O (io), 23 I/O (io), 24 I/O (io), 25 M1-~{RDATA} (out), 26 M0-RTRIG (in), 27 M2-I/O (io), 28 HDC-I/O (io), 29 I/O (io), 30 ~{LDC}-I/O (io), 31 I/O (io), 32 I/O (io), 33 I/O (io), 34 ~{INIT}-I/O (io), 35 GND (power), 36 I/O (io), 37 I/O (io), 38 I/O (io), 39 I/O (io), 40 I/O (io), 41 I/O (io), 42 I/O (io), 43 XTL2(IN)-I/O (io), 44 ~{RESET} (in), 45 DONE-~{PROG} (out), 46 D7-I/O (io), 47 XTL1(OUT)-BCLKIN-I/O (io), 48 D6-I/O (io), 49 D5-I/O (io), 50 ~{CS}0-I/O (io), 51 D4-I/O (io), 52 VCC (power), 53 D3-I/O (io), 54 ~{CS}1-I/O (io), 55 D2-I/O (io), 56 D1-I/O (io), 57 RDY/~{BUSY}-~{RCLK}-I/O (io), 58 DO-DIN-I/O (io), 59 DOUT-I/O (io), 60 CCLK (io), 61 A0-~{WS}-I/O (io), 62 A1-CS2-I/O (io), 63 A2-I/O (io), 64 A3-I/O (io), 65 A15-I/O (io), 66 A4-I/O (io), 67 A14-I/O (io), 68 A5-I/O (io)

## XC3120A-2PC68I
designator U?
Logic Cell Array with 64 CLBs, with 58 I/O Pins, 68-Pin PLCC, Industrial Grade; ComponentAvailability: Not for New Design
footprint PC68_N (Leaded Chip Carrier, 68-Leads, Body 24x24mm, Pitch 1.27mm, IPC Medium Density)
footprint PC68_L (Leaded Chip Carrier, 68-Leads, Body 24x24mm, Pitch 1.27mm, IPC High Density)
footprint PC68_M (Leaded Chip Carrier, 68-Leads, Body 24x24mm, Pitch 1.27mm, IPC Low Density)
3D model XC3120A-PC68 (68-Pin Plastic Leaded Chip Carrier (PC68))
pins: 1 GND (power), 2 A13-I/O (io), 3 A6-I/O (io), 4 A12-I/O (io), 5 A7-I/O (io), 6 A11-I/O (io), 7 A8-I/O (io), 8 A10-I/O (io), 9 A9-I/O (io), 10 ~{PWRDN} (in), 11 TCLKIN-I/O (io), 12 I/O (io), 13 I/O (io), 14 I/O (io), 15 I/O (io), 16 I/O (io), 17 I/O (io), 18 VCC (power), 19 I/O (io), 20 I/O (io), 21 I/O (io), 22 I/O (io), 23 I/O (io), 24 I/O (io), 25 M1-~{RDATA} (out), 26 M0-RTRIG (in), 27 M2-I/O (io), 28 HDC-I/O (io), 29 I/O (io), 30 ~{LDC}-I/O (io), 31 I/O (io), 32 I/O (io), 33 I/O (io), 34 ~{INIT}-I/O (io), 35 GND (power), 36 I/O (io), 37 I/O (io), 38 I/O (io), 39 I/O (io), 40 I/O (io), 41 I/O (io), 42 I/O (io), 43 XTL2(IN)-I/O (io), 44 ~{RESET} (in), 45 DONE-~{PROG} (out), 46 D7-I/O (io), 47 XTL1(OUT)-BCLKIN-I/O (io), 48 D6-I/O (io), 49 D5-I/O (io), 50 ~{CS}0-I/O (io), 51 D4-I/O (io), 52 VCC (power), 53 D3-I/O (io), 54 ~{CS}1-I/O (io), 55 D2-I/O (io), 56 D1-I/O (io), 57 RDY/~{BUSY}-~{RCLK}-I/O (io), 58 DO-DIN-I/O (io), 59 DOUT-I/O (io), 60 CCLK (io), 61 A0-~{WS}-I/O (io), 62 A1-CS2-I/O (io), 63 A2-I/O (io), 64 A3-I/O (io), 65 A15-I/O (io), 66 A4-I/O (io), 67 A14-I/O (io), 68 A5-I/O (io)

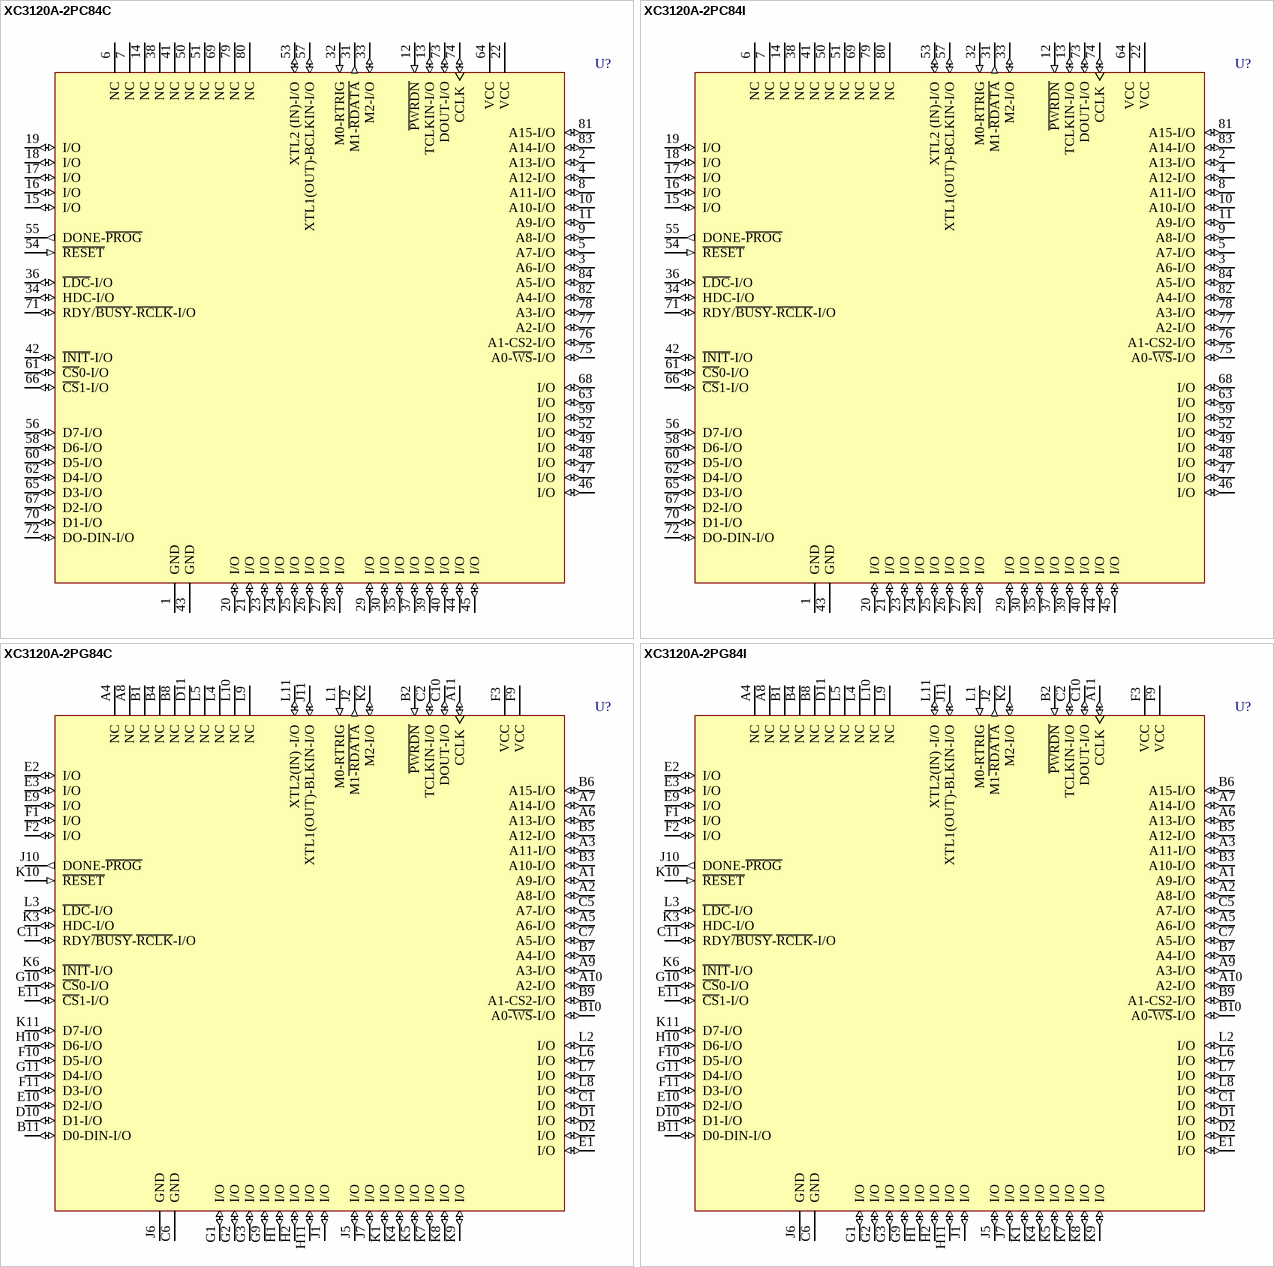
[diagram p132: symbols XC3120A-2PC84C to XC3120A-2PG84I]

## XC3120A-2PC84C
designator U?
Logic Cell Array with 64 CLBs, with 64 I/O Pins, 84-Pin PLCC, Commercial Grade; ComponentAvailability: Not for New Design
footprint PC84_N (Leaded Chip Carrier, 84-Leads, Body 29.3x29.3mm, Pitch 1.27mm, IPC Medium Density)
footprint PC84_L (Leaded Chip Carrier, 84-Leads, Body 29.3x29.3mm, Pitch 1.27mm, IPC High Density)
footprint PC84_M (Leaded Chip Carrier, 84-Leads, Body 29.3x29.3mm, Pitch 1.27mm, IPC Low Density)
3D model XC3120A-PC84 (84-Pin Plastic Leaded Chip Carrier (PC84))
pins: 1 GND (power), 2 A13-I/O (io), 3 A6-I/O (io), 4 A12-I/O (io), 5 A7-I/O (io), 6 NC, 7 NC, 8 A11-I/O (io), 9 A8-I/O (io), 10 A10-I/O (io), 11 A9-I/O (io), 12 ~{PWRDN} (in), 13 TCLKIN-I/O (io), 14 NC, 15 I/O (io), 16 I/O (io), 17 I/O (io), 18 I/O (io), 19 I/O (io), 20 I/O (io), 21 I/O (io), 22 VCC (power), 23 I/O (io), 24 I/O (io), 25 I/O (io), 26 I/O (io), 27 I/O (io), 28 I/O (io), 29 I/O (io), 30 I/O (io), 31 M1-~{RDATA} (out), 32 M0-RTRIG (in), 33 M2-I/O (io), 34 HDC-I/O (io), 35 I/O (io), 36 ~{LDC}-I/O (io), 37 I/O (io), 38 NC, 39 I/O (io), 40 I/O (io), 41 NC, 42 ~{INIT}-I/O (io), 43 GND (power), 44 I/O (io), 45 I/O (io), 46 I/O (io), 47 I/O (io), 48 I/O (io), 49 I/O (io), 50 NC, 51 NC, 52 I/O (io), 53 XTL2 (IN)-I/O (io), 54 ~{RESET} (in), 55 DONE-~{PROG} (out), 56 D7-I/O (io), 57 XTL1(OUT)-BCLKIN-I/O (io), 58 D6-I/O (io), 59 I/O (io), 60 D5-I/O (io), 61 ~{CS}0-I/O (io), 62 D4-I/O (io), 63 I/O (io), 64 VCC (power), 65 D3-I/O (io), 66 ~{CS}1-I/O (io), 67 D2-I/O (io), 68 I/O (io), 69 NC, 70 D1-I/O (io), 71 RDY/~{BUSY}-~{RCLK}-I/O (io), 72 DO-DIN-I/O (io), 73 DOUT-I/O (io), 74 CCLK (io), 75 A0-~{WS}-I/O (io), 76 A1-CS2-I/O (io), 77 A2-I/O (io), 78 A3-I/O (io), 79 NC, 80 NC, 81 A15-I/O (io), 82 A4-I/O (io), 83 A14-I/O (io), 84 A5-I/O (io)

## XC3120A-2PC84I
designator U?
Logic Cell Array with 64 CLBs, with 64 I/O Pins, 84-Pin PLCC, Industrial Grade; ComponentAvailability: Not for New Design
footprint PC84_N (Leaded Chip Carrier, 84-Leads, Body 29.3x29.3mm, Pitch 1.27mm, IPC Medium Density)
footprint PC84_L (Leaded Chip Carrier, 84-Leads, Body 29.3x29.3mm, Pitch 1.27mm, IPC High Density)
footprint PC84_M (Leaded Chip Carrier, 84-Leads, Body 29.3x29.3mm, Pitch 1.27mm, IPC Low Density)
3D model XC3120A-PC84 (84-Pin Plastic Leaded Chip Carrier (PC84))
pins: 1 GND (power), 2 A13-I/O (io), 3 A6-I/O (io), 4 A12-I/O (io), 5 A7-I/O (io), 6 NC, 7 NC, 8 A11-I/O (io), 9 A8-I/O (io), 10 A10-I/O (io), 11 A9-I/O (io), 12 ~{PWRDN} (in), 13 TCLKIN-I/O (io), 14 NC, 15 I/O (io), 16 I/O (io), 17 I/O (io), 18 I/O (io), 19 I/O (io), 20 I/O (io), 21 I/O (io), 22 VCC (power), 23 I/O (io), 24 I/O (io), 25 I/O (io), 26 I/O (io), 27 I/O (io), 28 I/O (io), 29 I/O (io), 30 I/O (io), 31 M1-~{RDATA} (out), 32 M0-RTRIG (in), 33 M2-I/O (io), 34 HDC-I/O (io), 35 I/O (io), 36 ~{LDC}-I/O (io), 37 I/O (io), 38 NC, 39 I/O (io), 40 I/O (io), 41 NC, 42 ~{INIT}-I/O (io), 43 GND (power), 44 I/O (io), 45 I/O (io), 46 I/O (io), 47 I/O (io), 48 I/O (io), 49 I/O (io), 50 NC, 51 NC, 52 I/O (io), 53 XTL2 (IN)-I/O (io), 54 ~{RESET} (in), 55 DONE-~{PROG} (out), 56 D7-I/O (io), 57 XTL1(OUT)-BCLKIN-I/O (io), 58 D6-I/O (io), 59 I/O (io), 60 D5-I/O (io), 61 ~{CS}0-I/O (io), 62 D4-I/O (io), 63 I/O (io), 64 VCC (power), 65 D3-I/O (io), 66 ~{CS}1-I/O (io), 67 D2-I/O (io), 68 I/O (io), 69 NC, 70 D1-I/O (io), 71 RDY/~{BUSY}-~{RCLK}-I/O (io), 72 DO-DIN-I/O (io), 73 DOUT-I/O (io), 74 CCLK (io), 75 A0-~{WS}-I/O (io), 76 A1-CS2-I/O (io), 77 A2-I/O (io), 78 A3-I/O (io), 79 NC, 80 NC, 81 A15-I/O (io), 82 A4-I/O (io), 83 A14-I/O (io), 84 A5-I/O (io)

## XC3120A-2PG84C
designator U?
Logic Cell Array with 64 CLBs, with 64 I/O Pins, 84-Pin PGA, Commercial Grade; ComponentAvailability: Not for New Design
footprint PG84 (PGA, 85-Leads, Body 28x28mm, Pitch 2.54mm)
3D model XC3120A-PG84 (84-Pin Ceramic Pin Grid Array (PG84))
pins: A1 A9-I/O (io), A2 A8-I/O (io), A3 A11-I/O (io), A4 NC, A5 A6-I/O (io), A6 A13-I/O (io), A7 A14-I/O (io), A8 NC, A9 A3-I/O (io), A10 A2-I/O (io), A11 CCLK (io), B1 NC, B2 ~{PWRDN} (in), B3 A10-I/O (io), B4 NC, B5 A12-I/O (io), B6 A15-I/O (io), B7 A4-I/O (io), B8 NC, B9 A1-CS2-I/O (io), B10 A0~{-WS}-I/O (io), B11 D0-DIN-I/O (io), C1 I/O (io), C2 TCLKIN-I/O (io), C5 A7-I/O (io), C6 GND (power), C7 A5-I/O (io), C10 DOUT-I/O (io), C11 RDY~{/BUSY}-~{RCLK}-I/O (io), D1 I/O (io), D2 I/O (io), D10 D1-I/O (io), D11 NC, E1 I/O (io), E2 I/O (io), E3 I/O (io), E9 I/O (io), E10 D2-I/O (io), E11 ~{CS}1-I/O (io), F1 I/O (io), F2 I/O (io), F3 VCC (power), F9 VCC (power), F10 D5-I/O (io), F11 D3-I/O (io), G1 I/O (io), G2 I/O (io), G3 I/O (io), G9 I/O (io), G10 ~{CS}0-I/O (io), G11 D4-I/O (io), H1 I/O (io), H2 I/O (io), H10 D6-I/O (io), H11 I/O (io), J1 I/O (io), J2 M1~{-RDATA} (out), J5 I/O (io), J6 GND (power), J7 I/O (io), J10 DONE-~{PROG} (out), J11 XTL1(OUT)-BLKIN-I/O (io), K1 I/O (io), K2 M2-I/O (io), K3 HDC-I/O (io), K4 I/O (io), K5 I/O (io), K6 ~{INIT}-I/O (io), K7 I/O (io), K8 I/O (io), K9 I/O (io), K10 ~{RESET} (in), K11 D7-I/O (io), L1 M0-RTRIG (in), L2 I/O (io), L3 ~{LDC}-I/O (io), L4 NC, L5 NC, L6 I/O (io), L7 I/O (io), L8 I/O (io), L9 NC, L10 NC, L11 XTL2(IN) -I/O (io)

## XC3120A-2PG84I
designator U?
Logic Cell Array with 64 CLBs, with 64 I/O Pins, 84-Pin PGA, Industrial Grade; ComponentAvailability: Not for New Design
footprint PG84 (PGA, 85-Leads, Body 28x28mm, Pitch 2.54mm)
3D model XC3120A-PG84 (84-Pin Ceramic Pin Grid Array (PG84))
pins: A1 A9-I/O (io), A2 A8-I/O (io), A3 A11-I/O (io), A4 NC, A5 A6-I/O (io), A6 A13-I/O (io), A7 A14-I/O (io), A8 NC, A9 A3-I/O (io), A10 A2-I/O (io), A11 CCLK (io), B1 NC, B2 ~{PWRDN} (in), B3 A10-I/O (io), B4 NC, B5 A12-I/O (io), B6 A15-I/O (io), B7 A4-I/O (io), B8 NC, B9 A1-CS2-I/O (io), B10 A0~{-WS}-I/O (io), B11 D0-DIN-I/O (io), C1 I/O (io), C2 TCLKIN-I/O (io), C5 A7-I/O (io), C6 GND (power), C7 A5-I/O (io), C10 DOUT-I/O (io), C11 RDY~{/BUSY}-~{RCLK}-I/O (io), D1 I/O (io), D2 I/O (io), D10 D1-I/O (io), D11 NC, E1 I/O (io), E2 I/O (io), E3 I/O (io), E9 I/O (io), E10 D2-I/O (io), E11 ~{CS}1-I/O (io), F1 I/O (io), F2 I/O (io), F3 VCC (power), F9 VCC (power), F10 D5-I/O (io), F11 D3-I/O (io), G1 I/O (io), G2 I/O (io), G3 I/O (io), G9 I/O (io), G10 ~{CS}0-I/O (io), G11 D4-I/O (io), H1 I/O (io), H2 I/O (io), H10 D6-I/O (io), H11 I/O (io), J1 I/O (io), J2 M1~{-RDATA} (out), J5 I/O (io), J6 GND (power), J7 I/O (io), J10 DONE-~{PROG} (out), J11 XTL1(OUT)-BLKIN-I/O (io), K1 I/O (io), K2 M2-I/O (io), K3 HDC-I/O (io), K4 I/O (io), K5 I/O (io), K6 ~{INIT}-I/O (io), K7 I/O (io), K8 I/O (io), K9 I/O (io), K10 ~{RESET} (in), K11 D7-I/O (io), L1 M0-RTRIG (in), L2 I/O (io), L3 ~{LDC}-I/O (io), L4 NC, L5 NC, L6 I/O (io), L7 I/O (io), L8 I/O (io), L9 NC, L10 NC, L11 XTL2(IN) -I/O (io)

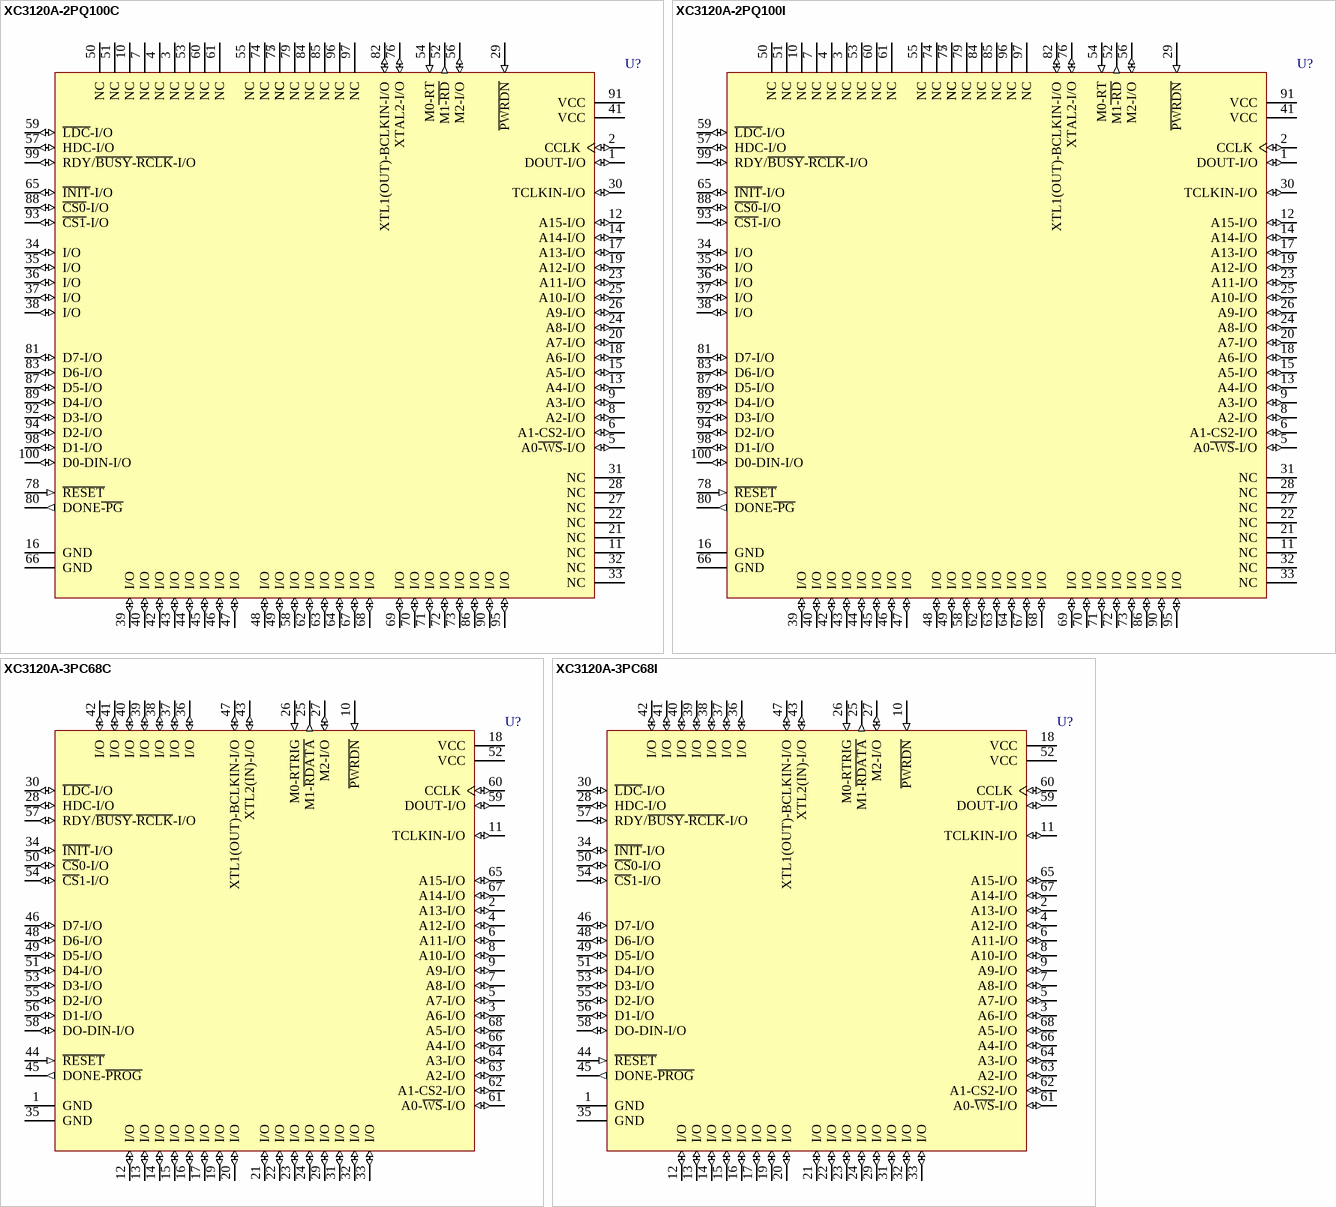
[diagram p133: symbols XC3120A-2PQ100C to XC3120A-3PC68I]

## XC3120A-2PQ100C
designator U?
Logic Cell Array with 64 CLBs, with 64 I/O Pins, 100-Pin PQFP, Commercial Grade; ComponentAvailability: Not for New Design
footprint PQ100_N (QFP, 100-Leads, Body 20x14mm, Pitch 0.65mm, IPC Medium Density)
footprint PQ100_L (QFP, 100-Leads, Body 20x14mm, Pitch 0.65mm, IPC High Density)
footprint PQ100_M (QFP, 100-Leads, Body 20x14mm, Pitch 0.65mm, IPC Low Density)
3D model XC3120A-PQ100 (100-Pin Plastic Quad Flat Pack (PQ100))
pins: 1 DOUT-I/O (io), 2 CCLK (io), 3 NC, 4 NC, 5 A0~{-WS}-I/O (io), 6 A1-CS2-I/O (io), 7 NC, 8 A2-I/O (io), 9 A3-I/O (io), 10 NC, 11 NC, 12 A15-I/O (io), 13 A4-I/O (io), 14 A14-I/O (io), 15 A5-I/O (io), 16 GND (power), 17 A13-I/O (io), 18 A6-I/O (io), 19 A12-I/O (io), 20 A7-I/O (io), 21 NC, 22 NC, 23 A11-I/O (io), 24 A8-I/O (io), 25 A10-I/O (io), 26 A9-I/O (io), 27 NC, 28 NC, 29 ~{PWRDN} (in), 30 TCLKIN-I/O (io), 31 NC, 32 NC, 33 NC, 34 I/O (io), 35 I/O (io), 36 I/O (io), 37 I/O (io), 38 I/O (io), 39 I/O (io), 40 I/O (io), 41 VCC (power), 42 I/O (io), 43 I/O (io), 44 I/O (io), 45 I/O (io), 46 I/O (io), 47 I/O (io), 48 I/O (io), 49 I/O (io), 50 NC, 51 NC, 52 M1~{-RD} (out), 53 NC, 54 M0-RT (in), 55 NC, 56 M2-I/O (io), 57 HDC-I/O (io), 58 I/O (io), 59 ~{LDC}-I/O (io), 60 NC, 61 NC, 62 I/O (io), 63 I/O (io), 64 I/O (io), 65 ~{INIT}-I/O (io), 66 GND (power), 67 I/O (io), 68 I/O (io), 69 I/O (io), 70 I/O (io), 71 I/O (io), 72 I/O (io), 73 I/O (io), 74 NC, 75 NC, 76 XTAL2-I/O (io), 77 NC, 78 ~{RESET} (in), 79 NC, 80 DONE~{-PG} (out), 81 D7-I/O (io), 82 XTL1(OUT)-BCLKIN-I/O (io), 83 D6-I/O (io), 84 NC, 85 NC, 86 I/O (io), 87 D5-I/O (io), 88 ~{CS0}-I/O (io), 89 D4-I/O (io), 90 I/O (io), 91 VCC (power), 92 D3-I/O (io), 93 ~{CS1}-I/O (io), 94 D2-I/O (io), 95 I/O (io), 96 NC, 97 NC, 98 D1-I/O (io), 99 RDY/~{BUSY}-~{RCLK}-I/O (io), 100 D0-DIN-I/O (io)

## XC3120A-2PQ100I
designator U?
Logic Cell Array with 64 CLBs, with 64 I/O Pins, 100-Pin PQFP, Industrial Grade; ComponentAvailability: Not for New Design
footprint PQ100_N (QFP, 100-Leads, Body 20x14mm, Pitch 0.65mm, IPC Medium Density)
footprint PQ100_L (QFP, 100-Leads, Body 20x14mm, Pitch 0.65mm, IPC High Density)
footprint PQ100_M (QFP, 100-Leads, Body 20x14mm, Pitch 0.65mm, IPC Low Density)
3D model XC3120A-PQ100 (100-Pin Plastic Quad Flat Pack (PQ100))
pins: 1 DOUT-I/O (io), 2 CCLK (io), 3 NC, 4 NC, 5 A0~{-WS}-I/O (io), 6 A1-CS2-I/O (io), 7 NC, 8 A2-I/O (io), 9 A3-I/O (io), 10 NC, 11 NC, 12 A15-I/O (io), 13 A4-I/O (io), 14 A14-I/O (io), 15 A5-I/O (io), 16 GND (power), 17 A13-I/O (io), 18 A6-I/O (io), 19 A12-I/O (io), 20 A7-I/O (io), 21 NC, 22 NC, 23 A11-I/O (io), 24 A8-I/O (io), 25 A10-I/O (io), 26 A9-I/O (io), 27 NC, 28 NC, 29 ~{PWRDN} (in), 30 TCLKIN-I/O (io), 31 NC, 32 NC, 33 NC, 34 I/O (io), 35 I/O (io), 36 I/O (io), 37 I/O (io), 38 I/O (io), 39 I/O (io), 40 I/O (io), 41 VCC (power), 42 I/O (io), 43 I/O (io), 44 I/O (io), 45 I/O (io), 46 I/O (io), 47 I/O (io), 48 I/O (io), 49 I/O (io), 50 NC, 51 NC, 52 M1~{-RD} (out), 53 NC, 54 M0-RT (in), 55 NC, 56 M2-I/O (io), 57 HDC-I/O (io), 58 I/O (io), 59 ~{LDC}-I/O (io), 60 NC, 61 NC, 62 I/O (io), 63 I/O (io), 64 I/O (io), 65 ~{INIT}-I/O (io), 66 GND (power), 67 I/O (io), 68 I/O (io), 69 I/O (io), 70 I/O (io), 71 I/O (io), 72 I/O (io), 73 I/O (io), 74 NC, 75 NC, 76 XTAL2-I/O (io), 77 NC, 78 ~{RESET} (in), 79 NC, 80 DONE~{-PG} (out), 81 D7-I/O (io), 82 XTL1(OUT)-BCLKIN-I/O (io), 83 D6-I/O (io), 84 NC, 85 NC, 86 I/O (io), 87 D5-I/O (io), 88 ~{CS0}-I/O (io), 89 D4-I/O (io), 90 I/O (io), 91 VCC (power), 92 D3-I/O (io), 93 ~{CS1}-I/O (io), 94 D2-I/O (io), 95 I/O (io), 96 NC, 97 NC, 98 D1-I/O (io), 99 RDY/~{BUSY}-~{RCLK}-I/O (io), 100 D0-DIN-I/O (io)

## XC3120A-3PC68C
designator U?
Logic Cell Array with 64 CLBs, with 58 I/O Pins, 68-Pin PLCC, Commercial Grade; ComponentAvailability: Not for New Design
footprint PC68_N (Leaded Chip Carrier, 68-Leads, Body 24x24mm, Pitch 1.27mm, IPC Medium Density)
footprint PC68_L (Leaded Chip Carrier, 68-Leads, Body 24x24mm, Pitch 1.27mm, IPC High Density)
footprint PC68_M (Leaded Chip Carrier, 68-Leads, Body 24x24mm, Pitch 1.27mm, IPC Low Density)
3D model XC3120A-PC68 (68-Pin Plastic Leaded Chip Carrier (PC68))
pins: 1 GND (power), 2 A13-I/O (io), 3 A6-I/O (io), 4 A12-I/O (io), 5 A7-I/O (io), 6 A11-I/O (io), 7 A8-I/O (io), 8 A10-I/O (io), 9 A9-I/O (io), 10 ~{PWRDN} (in), 11 TCLKIN-I/O (io), 12 I/O (io), 13 I/O (io), 14 I/O (io), 15 I/O (io), 16 I/O (io), 17 I/O (io), 18 VCC (power), 19 I/O (io), 20 I/O (io), 21 I/O (io), 22 I/O (io), 23 I/O (io), 24 I/O (io), 25 M1-~{RDATA} (out), 26 M0-RTRIG (in), 27 M2-I/O (io), 28 HDC-I/O (io), 29 I/O (io), 30 ~{LDC}-I/O (io), 31 I/O (io), 32 I/O (io), 33 I/O (io), 34 ~{INIT}-I/O (io), 35 GND (power), 36 I/O (io), 37 I/O (io), 38 I/O (io), 39 I/O (io), 40 I/O (io), 41 I/O (io), 42 I/O (io), 43 XTL2(IN)-I/O (io), 44 ~{RESET} (in), 45 DONE-~{PROG} (out), 46 D7-I/O (io), 47 XTL1(OUT)-BCLKIN-I/O (io), 48 D6-I/O (io), 49 D5-I/O (io), 50 ~{CS}0-I/O (io), 51 D4-I/O (io), 52 VCC (power), 53 D3-I/O (io), 54 ~{CS}1-I/O (io), 55 D2-I/O (io), 56 D1-I/O (io), 57 RDY/~{BUSY}-~{RCLK}-I/O (io), 58 DO-DIN-I/O (io), 59 DOUT-I/O (io), 60 CCLK (io), 61 A0-~{WS}-I/O (io), 62 A1-CS2-I/O (io), 63 A2-I/O (io), 64 A3-I/O (io), 65 A15-I/O (io), 66 A4-I/O (io), 67 A14-I/O (io), 68 A5-I/O (io)

## XC3120A-3PC68I
designator U?
Logic Cell Array with 64 CLBs, with 58 I/O Pins, 68-Pin PLCC, Industrial Grade; ComponentAvailability: Not for New Design
footprint PC68_N (Leaded Chip Carrier, 68-Leads, Body 24x24mm, Pitch 1.27mm, IPC Medium Density)
footprint PC68_L (Leaded Chip Carrier, 68-Leads, Body 24x24mm, Pitch 1.27mm, IPC High Density)
footprint PC68_M (Leaded Chip Carrier, 68-Leads, Body 24x24mm, Pitch 1.27mm, IPC Low Density)
3D model XC3120A-PC68 (68-Pin Plastic Leaded Chip Carrier (PC68))
pins: 1 GND (power), 2 A13-I/O (io), 3 A6-I/O (io), 4 A12-I/O (io), 5 A7-I/O (io), 6 A11-I/O (io), 7 A8-I/O (io), 8 A10-I/O (io), 9 A9-I/O (io), 10 ~{PWRDN} (in), 11 TCLKIN-I/O (io), 12 I/O (io), 13 I/O (io), 14 I/O (io), 15 I/O (io), 16 I/O (io), 17 I/O (io), 18 VCC (power), 19 I/O (io), 20 I/O (io), 21 I/O (io), 22 I/O (io), 23 I/O (io), 24 I/O (io), 25 M1-~{RDATA} (out), 26 M0-RTRIG (in), 27 M2-I/O (io), 28 HDC-I/O (io), 29 I/O (io), 30 ~{LDC}-I/O (io), 31 I/O (io), 32 I/O (io), 33 I/O (io), 34 ~{INIT}-I/O (io), 35 GND (power), 36 I/O (io), 37 I/O (io), 38 I/O (io), 39 I/O (io), 40 I/O (io), 41 I/O (io), 42 I/O (io), 43 XTL2(IN)-I/O (io), 44 ~{RESET} (in), 45 DONE-~{PROG} (out), 46 D7-I/O (io), 47 XTL1(OUT)-BCLKIN-I/O (io), 48 D6-I/O (io), 49 D5-I/O (io), 50 ~{CS}0-I/O (io), 51 D4-I/O (io), 52 VCC (power), 53 D3-I/O (io), 54 ~{CS}1-I/O (io), 55 D2-I/O (io), 56 D1-I/O (io), 57 RDY/~{BUSY}-~{RCLK}-I/O (io), 58 DO-DIN-I/O (io), 59 DOUT-I/O (io), 60 CCLK (io), 61 A0-~{WS}-I/O (io), 62 A1-CS2-I/O (io), 63 A2-I/O (io), 64 A3-I/O (io), 65 A15-I/O (io), 66 A4-I/O (io), 67 A14-I/O (io), 68 A5-I/O (io)

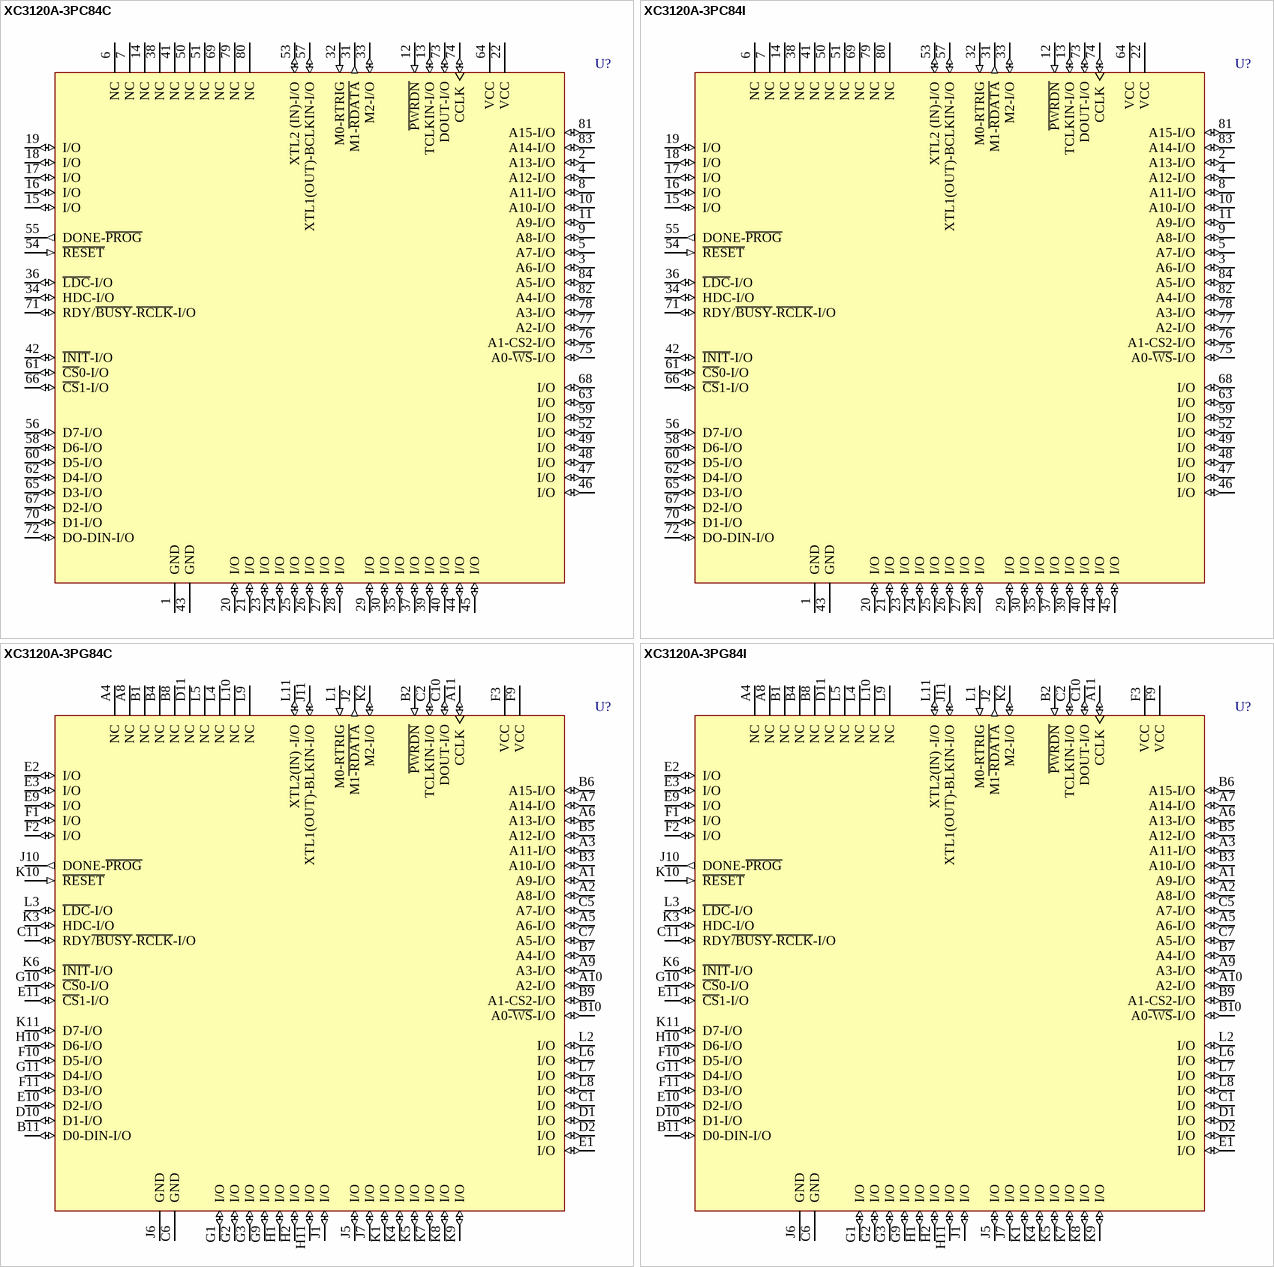
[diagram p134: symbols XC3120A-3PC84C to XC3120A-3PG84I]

## XC3120A-3PC84C
designator U?
Logic Cell Array with 64 CLBs, with 64 I/O Pins, 84-Pin PLCC, Commercial Grade; ComponentAvailability: Not for New Design
footprint PC84_N (Leaded Chip Carrier, 84-Leads, Body 29.3x29.3mm, Pitch 1.27mm, IPC Medium Density)
footprint PC84_L (Leaded Chip Carrier, 84-Leads, Body 29.3x29.3mm, Pitch 1.27mm, IPC High Density)
footprint PC84_M (Leaded Chip Carrier, 84-Leads, Body 29.3x29.3mm, Pitch 1.27mm, IPC Low Density)
3D model XC3120A-PC84 (84-Pin Plastic Leaded Chip Carrier (PC84))
pins: 1 GND (power), 2 A13-I/O (io), 3 A6-I/O (io), 4 A12-I/O (io), 5 A7-I/O (io), 6 NC, 7 NC, 8 A11-I/O (io), 9 A8-I/O (io), 10 A10-I/O (io), 11 A9-I/O (io), 12 ~{PWRDN} (in), 13 TCLKIN-I/O (io), 14 NC, 15 I/O (io), 16 I/O (io), 17 I/O (io), 18 I/O (io), 19 I/O (io), 20 I/O (io), 21 I/O (io), 22 VCC (power), 23 I/O (io), 24 I/O (io), 25 I/O (io), 26 I/O (io), 27 I/O (io), 28 I/O (io), 29 I/O (io), 30 I/O (io), 31 M1-~{RDATA} (out), 32 M0-RTRIG (in), 33 M2-I/O (io), 34 HDC-I/O (io), 35 I/O (io), 36 ~{LDC}-I/O (io), 37 I/O (io), 38 NC, 39 I/O (io), 40 I/O (io), 41 NC, 42 ~{INIT}-I/O (io), 43 GND (power), 44 I/O (io), 45 I/O (io), 46 I/O (io), 47 I/O (io), 48 I/O (io), 49 I/O (io), 50 NC, 51 NC, 52 I/O (io), 53 XTL2 (IN)-I/O (io), 54 ~{RESET} (in), 55 DONE-~{PROG} (out), 56 D7-I/O (io), 57 XTL1(OUT)-BCLKIN-I/O (io), 58 D6-I/O (io), 59 I/O (io), 60 D5-I/O (io), 61 ~{CS}0-I/O (io), 62 D4-I/O (io), 63 I/O (io), 64 VCC (power), 65 D3-I/O (io), 66 ~{CS}1-I/O (io), 67 D2-I/O (io), 68 I/O (io), 69 NC, 70 D1-I/O (io), 71 RDY/~{BUSY}-~{RCLK}-I/O (io), 72 DO-DIN-I/O (io), 73 DOUT-I/O (io), 74 CCLK (io), 75 A0-~{WS}-I/O (io), 76 A1-CS2-I/O (io), 77 A2-I/O (io), 78 A3-I/O (io), 79 NC, 80 NC, 81 A15-I/O (io), 82 A4-I/O (io), 83 A14-I/O (io), 84 A5-I/O (io)

## XC3120A-3PC84I
designator U?
Logic Cell Array with 64 CLBs, with 64 I/O Pins, 84-Pin PLCC, Industrial Grade; ComponentAvailability: Not for New Design
footprint PC84_N (Leaded Chip Carrier, 84-Leads, Body 29.3x29.3mm, Pitch 1.27mm, IPC Medium Density)
footprint PC84_L (Leaded Chip Carrier, 84-Leads, Body 29.3x29.3mm, Pitch 1.27mm, IPC High Density)
footprint PC84_M (Leaded Chip Carrier, 84-Leads, Body 29.3x29.3mm, Pitch 1.27mm, IPC Low Density)
3D model XC3120A-PC84 (84-Pin Plastic Leaded Chip Carrier (PC84))
pins: 1 GND (power), 2 A13-I/O (io), 3 A6-I/O (io), 4 A12-I/O (io), 5 A7-I/O (io), 6 NC, 7 NC, 8 A11-I/O (io), 9 A8-I/O (io), 10 A10-I/O (io), 11 A9-I/O (io), 12 ~{PWRDN} (in), 13 TCLKIN-I/O (io), 14 NC, 15 I/O (io), 16 I/O (io), 17 I/O (io), 18 I/O (io), 19 I/O (io), 20 I/O (io), 21 I/O (io), 22 VCC (power), 23 I/O (io), 24 I/O (io), 25 I/O (io), 26 I/O (io), 27 I/O (io), 28 I/O (io), 29 I/O (io), 30 I/O (io), 31 M1-~{RDATA} (out), 32 M0-RTRIG (in), 33 M2-I/O (io), 34 HDC-I/O (io), 35 I/O (io), 36 ~{LDC}-I/O (io), 37 I/O (io), 38 NC, 39 I/O (io), 40 I/O (io), 41 NC, 42 ~{INIT}-I/O (io), 43 GND (power), 44 I/O (io), 45 I/O (io), 46 I/O (io), 47 I/O (io), 48 I/O (io), 49 I/O (io), 50 NC, 51 NC, 52 I/O (io), 53 XTL2 (IN)-I/O (io), 54 ~{RESET} (in), 55 DONE-~{PROG} (out), 56 D7-I/O (io), 57 XTL1(OUT)-BCLKIN-I/O (io), 58 D6-I/O (io), 59 I/O (io), 60 D5-I/O (io), 61 ~{CS}0-I/O (io), 62 D4-I/O (io), 63 I/O (io), 64 VCC (power), 65 D3-I/O (io), 66 ~{CS}1-I/O (io), 67 D2-I/O (io), 68 I/O (io), 69 NC, 70 D1-I/O (io), 71 RDY/~{BUSY}-~{RCLK}-I/O (io), 72 DO-DIN-I/O (io), 73 DOUT-I/O (io), 74 CCLK (io), 75 A0-~{WS}-I/O (io), 76 A1-CS2-I/O (io), 77 A2-I/O (io), 78 A3-I/O (io), 79 NC, 80 NC, 81 A15-I/O (io), 82 A4-I/O (io), 83 A14-I/O (io), 84 A5-I/O (io)

## XC3120A-3PG84C
designator U?
Logic Cell Array with 64 CLBs, with 64 I/O Pins, 84-Pin PGA, Commercial Grade; ComponentAvailability: Not for New Design
footprint PG84 (PGA, 85-Leads, Body 28x28mm, Pitch 2.54mm)
3D model XC3120A-PG84 (84-Pin Ceramic Pin Grid Array (PG84))
pins: A1 A9-I/O (io), A2 A8-I/O (io), A3 A11-I/O (io), A4 NC, A5 A6-I/O (io), A6 A13-I/O (io), A7 A14-I/O (io), A8 NC, A9 A3-I/O (io), A10 A2-I/O (io), A11 CCLK (io), B1 NC, B2 ~{PWRDN} (in), B3 A10-I/O (io), B4 NC, B5 A12-I/O (io), B6 A15-I/O (io), B7 A4-I/O (io), B8 NC, B9 A1-CS2-I/O (io), B10 A0~{-WS}-I/O (io), B11 D0-DIN-I/O (io), C1 I/O (io), C2 TCLKIN-I/O (io), C5 A7-I/O (io), C6 GND (power), C7 A5-I/O (io), C10 DOUT-I/O (io), C11 RDY~{/BUSY}-~{RCLK}-I/O (io), D1 I/O (io), D2 I/O (io), D10 D1-I/O (io), D11 NC, E1 I/O (io), E2 I/O (io), E3 I/O (io), E9 I/O (io), E10 D2-I/O (io), E11 ~{CS}1-I/O (io), F1 I/O (io), F2 I/O (io), F3 VCC (power), F9 VCC (power), F10 D5-I/O (io), F11 D3-I/O (io), G1 I/O (io), G2 I/O (io), G3 I/O (io), G9 I/O (io), G10 ~{CS}0-I/O (io), G11 D4-I/O (io), H1 I/O (io), H2 I/O (io), H10 D6-I/O (io), H11 I/O (io), J1 I/O (io), J2 M1~{-RDATA} (out), J5 I/O (io), J6 GND (power), J7 I/O (io), J10 DONE-~{PROG} (out), J11 XTL1(OUT)-BLKIN-I/O (io), K1 I/O (io), K2 M2-I/O (io), K3 HDC-I/O (io), K4 I/O (io), K5 I/O (io), K6 ~{INIT}-I/O (io), K7 I/O (io), K8 I/O (io), K9 I/O (io), K10 ~{RESET} (in), K11 D7-I/O (io), L1 M0-RTRIG (in), L2 I/O (io), L3 ~{LDC}-I/O (io), L4 NC, L5 NC, L6 I/O (io), L7 I/O (io), L8 I/O (io), L9 NC, L10 NC, L11 XTL2(IN) -I/O (io)

## XC3120A-3PG84I
designator U?
Logic Cell Array with 64 CLBs, with 64 I/O Pins, 84-Pin PGA, Industrial Grade; ComponentAvailability: Not for New Design
footprint PG84 (PGA, 85-Leads, Body 28x28mm, Pitch 2.54mm)
3D model XC3120A-PG84 (84-Pin Ceramic Pin Grid Array (PG84))
pins: A1 A9-I/O (io), A2 A8-I/O (io), A3 A11-I/O (io), A4 NC, A5 A6-I/O (io), A6 A13-I/O (io), A7 A14-I/O (io), A8 NC, A9 A3-I/O (io), A10 A2-I/O (io), A11 CCLK (io), B1 NC, B2 ~{PWRDN} (in), B3 A10-I/O (io), B4 NC, B5 A12-I/O (io), B6 A15-I/O (io), B7 A4-I/O (io), B8 NC, B9 A1-CS2-I/O (io), B10 A0~{-WS}-I/O (io), B11 D0-DIN-I/O (io), C1 I/O (io), C2 TCLKIN-I/O (io), C5 A7-I/O (io), C6 GND (power), C7 A5-I/O (io), C10 DOUT-I/O (io), C11 RDY~{/BUSY}-~{RCLK}-I/O (io), D1 I/O (io), D2 I/O (io), D10 D1-I/O (io), D11 NC, E1 I/O (io), E2 I/O (io), E3 I/O (io), E9 I/O (io), E10 D2-I/O (io), E11 ~{CS}1-I/O (io), F1 I/O (io), F2 I/O (io), F3 VCC (power), F9 VCC (power), F10 D5-I/O (io), F11 D3-I/O (io), G1 I/O (io), G2 I/O (io), G3 I/O (io), G9 I/O (io), G10 ~{CS}0-I/O (io), G11 D4-I/O (io), H1 I/O (io), H2 I/O (io), H10 D6-I/O (io), H11 I/O (io), J1 I/O (io), J2 M1~{-RDATA} (out), J5 I/O (io), J6 GND (power), J7 I/O (io), J10 DONE-~{PROG} (out), J11 XTL1(OUT)-BLKIN-I/O (io), K1 I/O (io), K2 M2-I/O (io), K3 HDC-I/O (io), K4 I/O (io), K5 I/O (io), K6 ~{INIT}-I/O (io), K7 I/O (io), K8 I/O (io), K9 I/O (io), K10 ~{RESET} (in), K11 D7-I/O (io), L1 M0-RTRIG (in), L2 I/O (io), L3 ~{LDC}-I/O (io), L4 NC, L5 NC, L6 I/O (io), L7 I/O (io), L8 I/O (io), L9 NC, L10 NC, L11 XTL2(IN) -I/O (io)

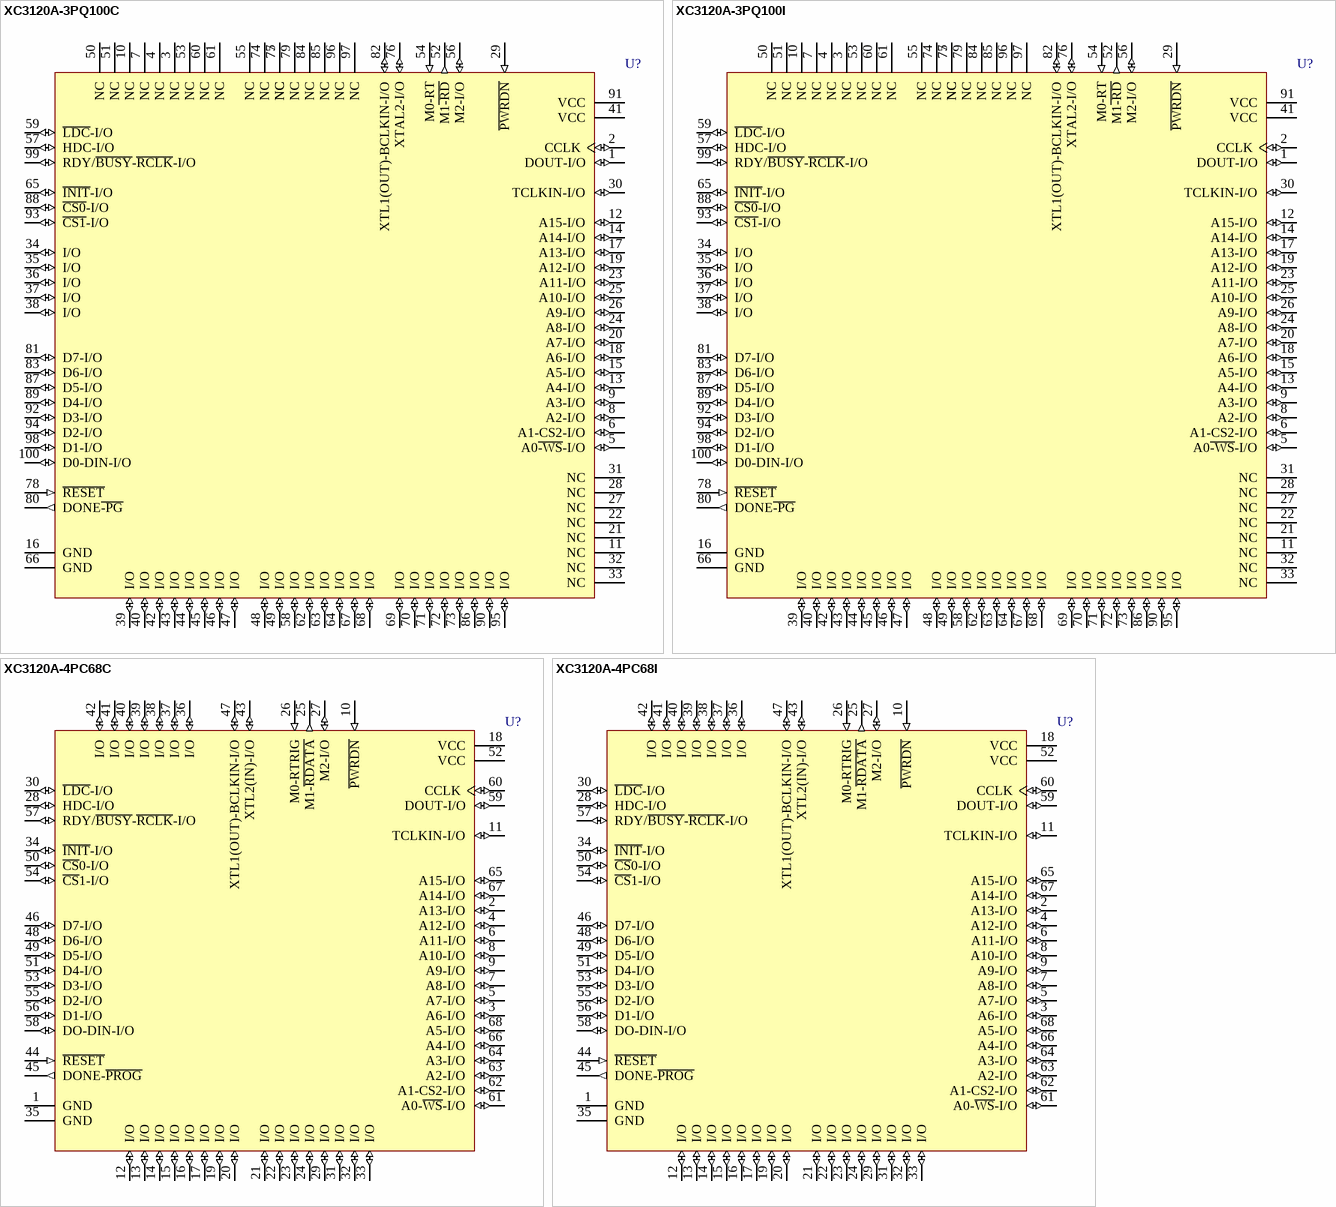
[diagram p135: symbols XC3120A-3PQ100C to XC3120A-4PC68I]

## XC3120A-3PQ100C
designator U?
Logic Cell Array with 64 CLBs, with 64 I/O Pins, 100-Pin PQFP, Commercial Grade; ComponentAvailability: Not for New Design
footprint PQ100_N (QFP, 100-Leads, Body 20x14mm, Pitch 0.65mm, IPC Medium Density)
footprint PQ100_L (QFP, 100-Leads, Body 20x14mm, Pitch 0.65mm, IPC High Density)
footprint PQ100_M (QFP, 100-Leads, Body 20x14mm, Pitch 0.65mm, IPC Low Density)
3D model XC3120A-PQ100 (100-Pin Plastic Quad Flat Pack (PQ100))
pins: 1 DOUT-I/O (io), 2 CCLK (io), 3 NC, 4 NC, 5 A0~{-WS}-I/O (io), 6 A1-CS2-I/O (io), 7 NC, 8 A2-I/O (io), 9 A3-I/O (io), 10 NC, 11 NC, 12 A15-I/O (io), 13 A4-I/O (io), 14 A14-I/O (io), 15 A5-I/O (io), 16 GND (power), 17 A13-I/O (io), 18 A6-I/O (io), 19 A12-I/O (io), 20 A7-I/O (io), 21 NC, 22 NC, 23 A11-I/O (io), 24 A8-I/O (io), 25 A10-I/O (io), 26 A9-I/O (io), 27 NC, 28 NC, 29 ~{PWRDN} (in), 30 TCLKIN-I/O (io), 31 NC, 32 NC, 33 NC, 34 I/O (io), 35 I/O (io), 36 I/O (io), 37 I/O (io), 38 I/O (io), 39 I/O (io), 40 I/O (io), 41 VCC (power), 42 I/O (io), 43 I/O (io), 44 I/O (io), 45 I/O (io), 46 I/O (io), 47 I/O (io), 48 I/O (io), 49 I/O (io), 50 NC, 51 NC, 52 M1~{-RD} (out), 53 NC, 54 M0-RT (in), 55 NC, 56 M2-I/O (io), 57 HDC-I/O (io), 58 I/O (io), 59 ~{LDC}-I/O (io), 60 NC, 61 NC, 62 I/O (io), 63 I/O (io), 64 I/O (io), 65 ~{INIT}-I/O (io), 66 GND (power), 67 I/O (io), 68 I/O (io), 69 I/O (io), 70 I/O (io), 71 I/O (io), 72 I/O (io), 73 I/O (io), 74 NC, 75 NC, 76 XTAL2-I/O (io), 77 NC, 78 ~{RESET} (in), 79 NC, 80 DONE~{-PG} (out), 81 D7-I/O (io), 82 XTL1(OUT)-BCLKIN-I/O (io), 83 D6-I/O (io), 84 NC, 85 NC, 86 I/O (io), 87 D5-I/O (io), 88 ~{CS0}-I/O (io), 89 D4-I/O (io), 90 I/O (io), 91 VCC (power), 92 D3-I/O (io), 93 ~{CS1}-I/O (io), 94 D2-I/O (io), 95 I/O (io), 96 NC, 97 NC, 98 D1-I/O (io), 99 RDY/~{BUSY}-~{RCLK}-I/O (io), 100 D0-DIN-I/O (io)

## XC3120A-3PQ100I
designator U?
Logic Cell Array with 64 CLBs, with 64 I/O Pins, 100-Pin PQFP, Industrial Grade; ComponentAvailability: Not for New Design
footprint PQ100_N (QFP, 100-Leads, Body 20x14mm, Pitch 0.65mm, IPC Medium Density)
footprint PQ100_L (QFP, 100-Leads, Body 20x14mm, Pitch 0.65mm, IPC High Density)
footprint PQ100_M (QFP, 100-Leads, Body 20x14mm, Pitch 0.65mm, IPC Low Density)
3D model XC3120A-PQ100 (100-Pin Plastic Quad Flat Pack (PQ100))
pins: 1 DOUT-I/O (io), 2 CCLK (io), 3 NC, 4 NC, 5 A0~{-WS}-I/O (io), 6 A1-CS2-I/O (io), 7 NC, 8 A2-I/O (io), 9 A3-I/O (io), 10 NC, 11 NC, 12 A15-I/O (io), 13 A4-I/O (io), 14 A14-I/O (io), 15 A5-I/O (io), 16 GND (power), 17 A13-I/O (io), 18 A6-I/O (io), 19 A12-I/O (io), 20 A7-I/O (io), 21 NC, 22 NC, 23 A11-I/O (io), 24 A8-I/O (io), 25 A10-I/O (io), 26 A9-I/O (io), 27 NC, 28 NC, 29 ~{PWRDN} (in), 30 TCLKIN-I/O (io), 31 NC, 32 NC, 33 NC, 34 I/O (io), 35 I/O (io), 36 I/O (io), 37 I/O (io), 38 I/O (io), 39 I/O (io), 40 I/O (io), 41 VCC (power), 42 I/O (io), 43 I/O (io), 44 I/O (io), 45 I/O (io), 46 I/O (io), 47 I/O (io), 48 I/O (io), 49 I/O (io), 50 NC, 51 NC, 52 M1~{-RD} (out), 53 NC, 54 M0-RT (in), 55 NC, 56 M2-I/O (io), 57 HDC-I/O (io), 58 I/O (io), 59 ~{LDC}-I/O (io), 60 NC, 61 NC, 62 I/O (io), 63 I/O (io), 64 I/O (io), 65 ~{INIT}-I/O (io), 66 GND (power), 67 I/O (io), 68 I/O (io), 69 I/O (io), 70 I/O (io), 71 I/O (io), 72 I/O (io), 73 I/O (io), 74 NC, 75 NC, 76 XTAL2-I/O (io), 77 NC, 78 ~{RESET} (in), 79 NC, 80 DONE~{-PG} (out), 81 D7-I/O (io), 82 XTL1(OUT)-BCLKIN-I/O (io), 83 D6-I/O (io), 84 NC, 85 NC, 86 I/O (io), 87 D5-I/O (io), 88 ~{CS0}-I/O (io), 89 D4-I/O (io), 90 I/O (io), 91 VCC (power), 92 D3-I/O (io), 93 ~{CS1}-I/O (io), 94 D2-I/O (io), 95 I/O (io), 96 NC, 97 NC, 98 D1-I/O (io), 99 RDY/~{BUSY}-~{RCLK}-I/O (io), 100 D0-DIN-I/O (io)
